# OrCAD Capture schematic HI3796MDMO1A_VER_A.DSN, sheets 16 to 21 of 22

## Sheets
16 SHEET_16: size Custom
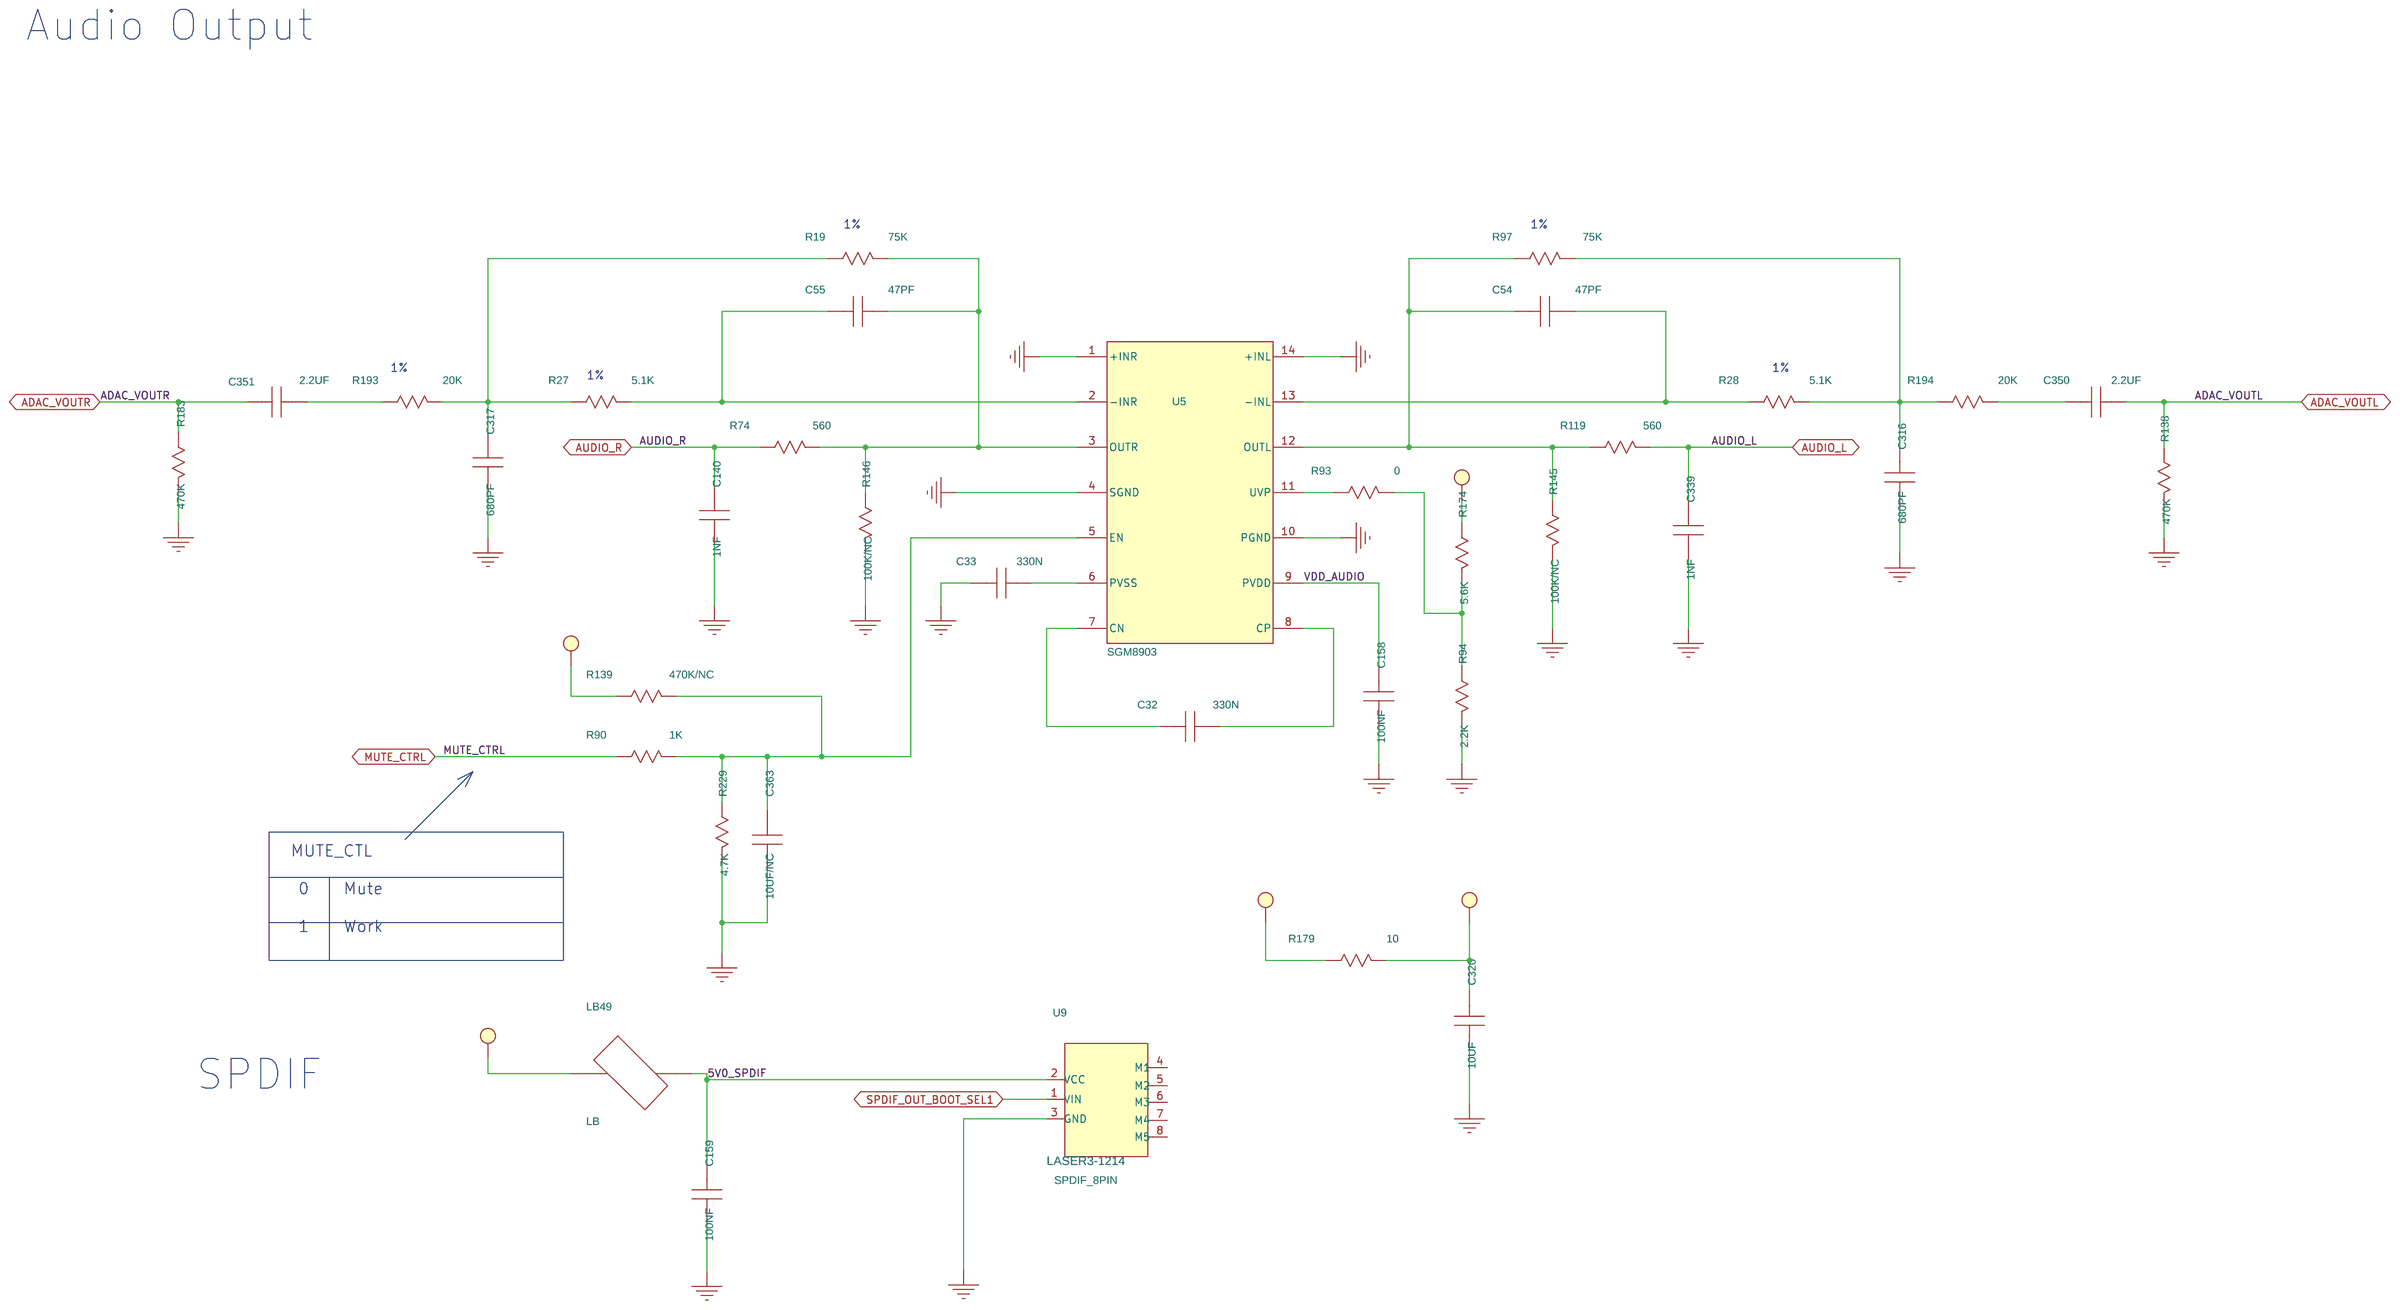
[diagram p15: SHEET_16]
17 SHEET_17: size B
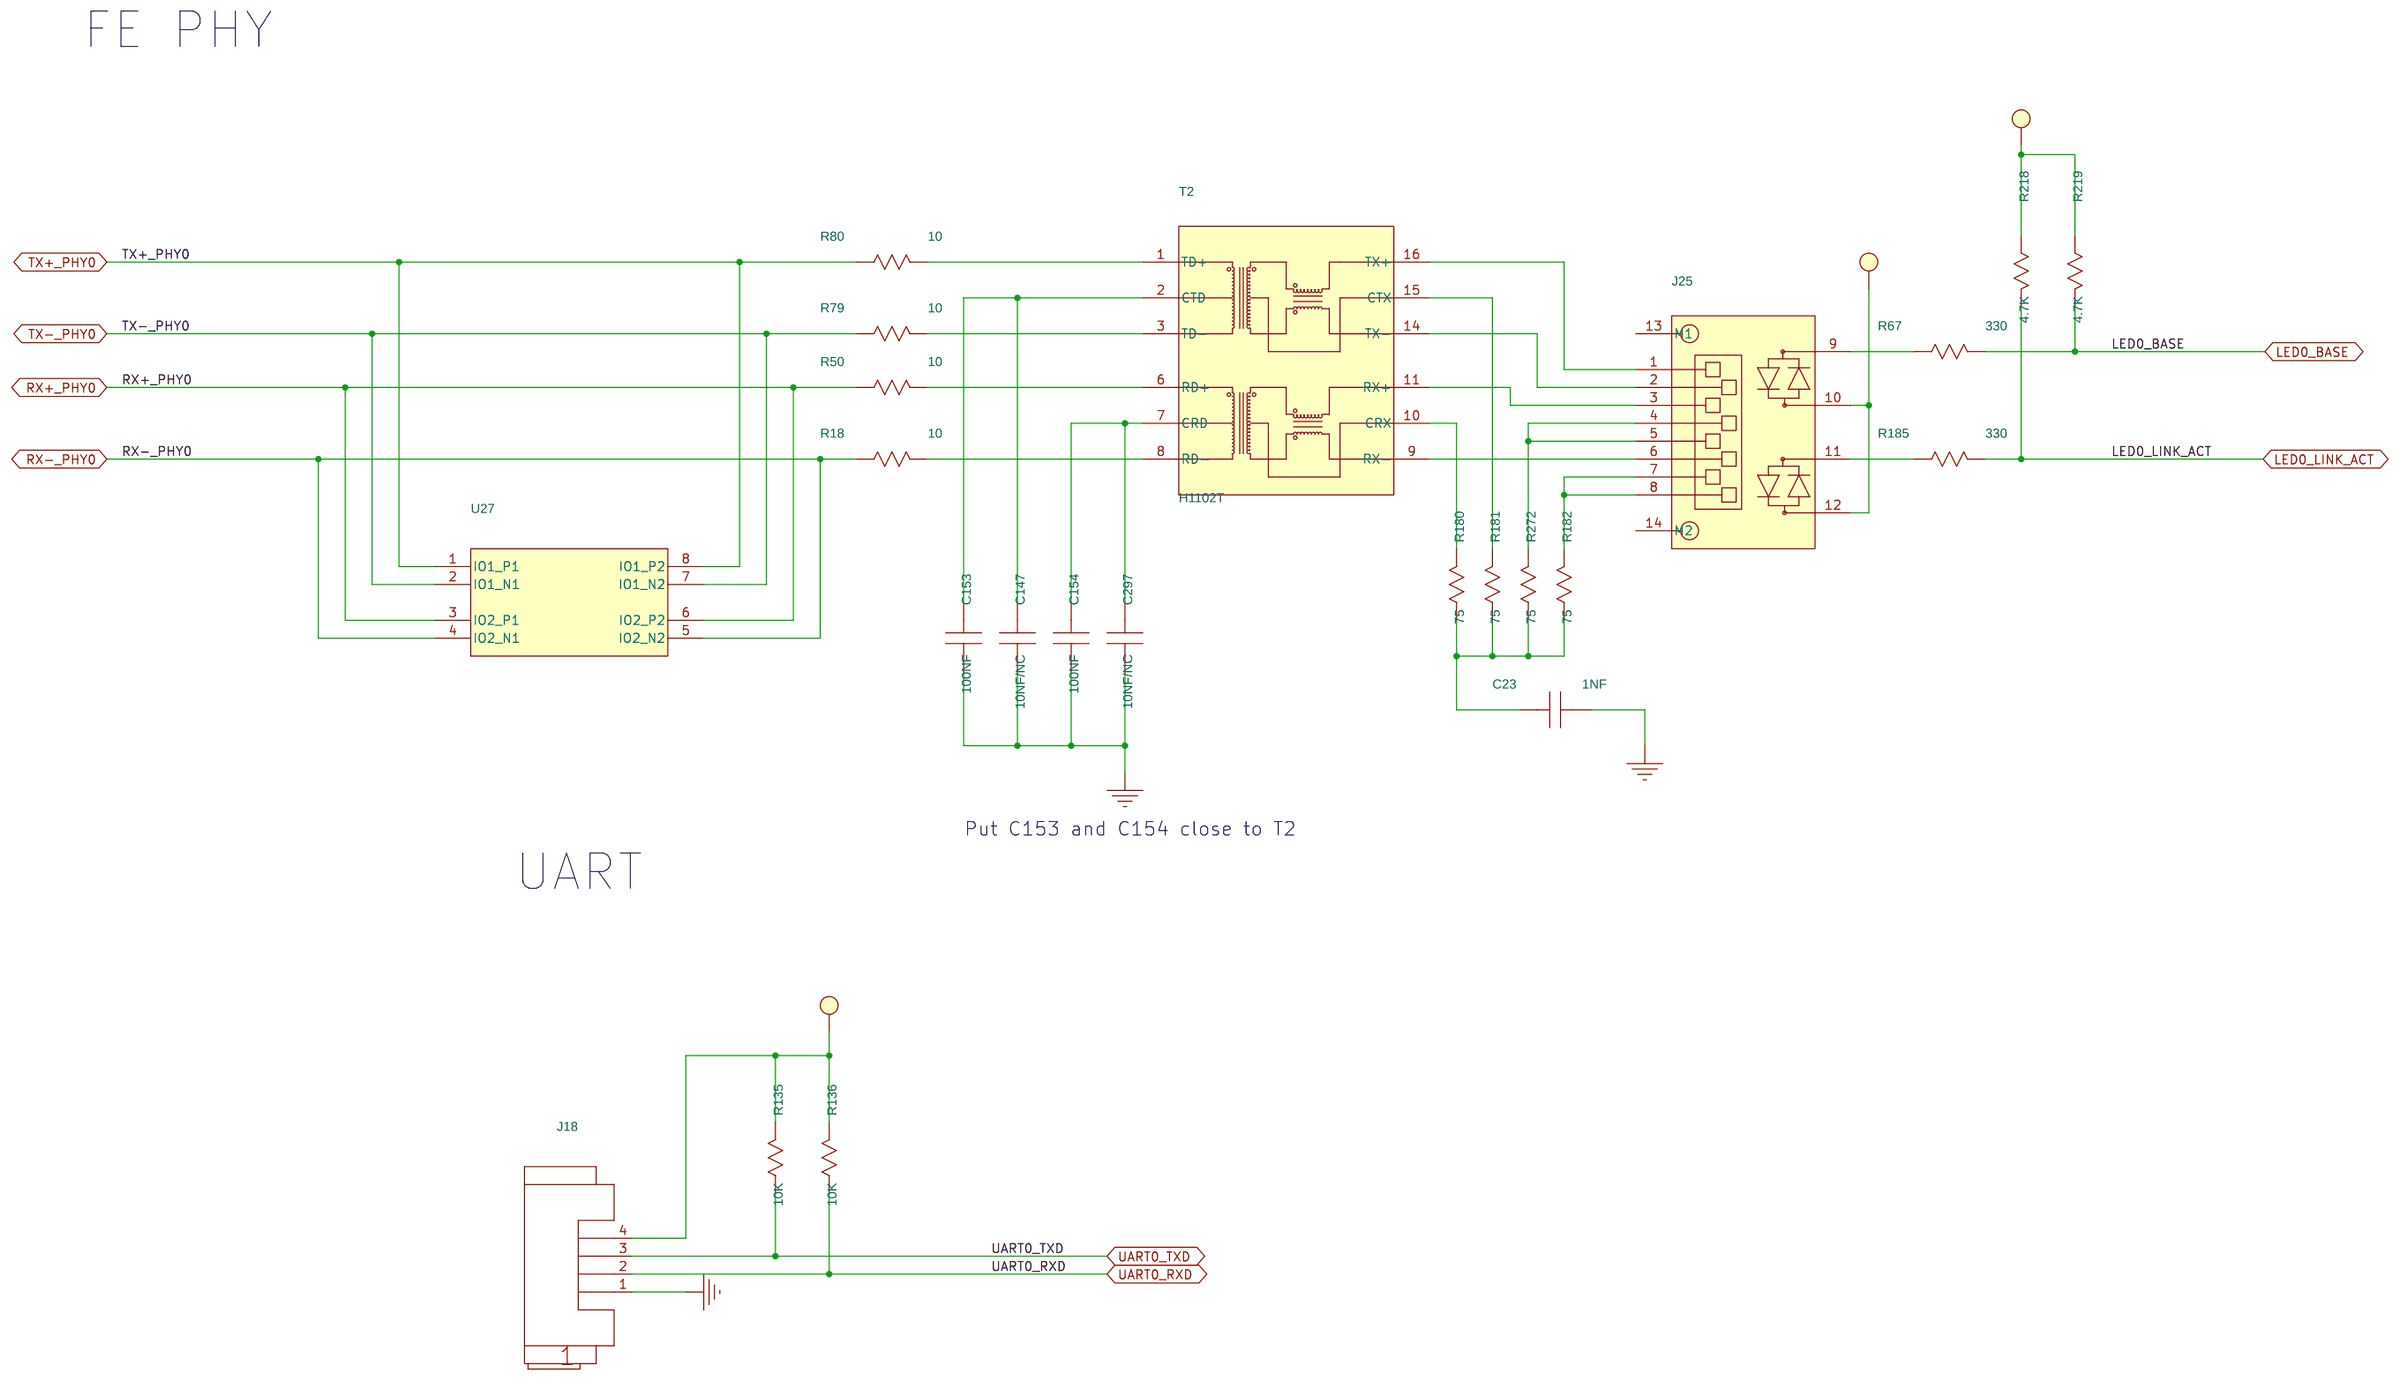
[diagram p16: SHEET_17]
18 SHEET_18: size B
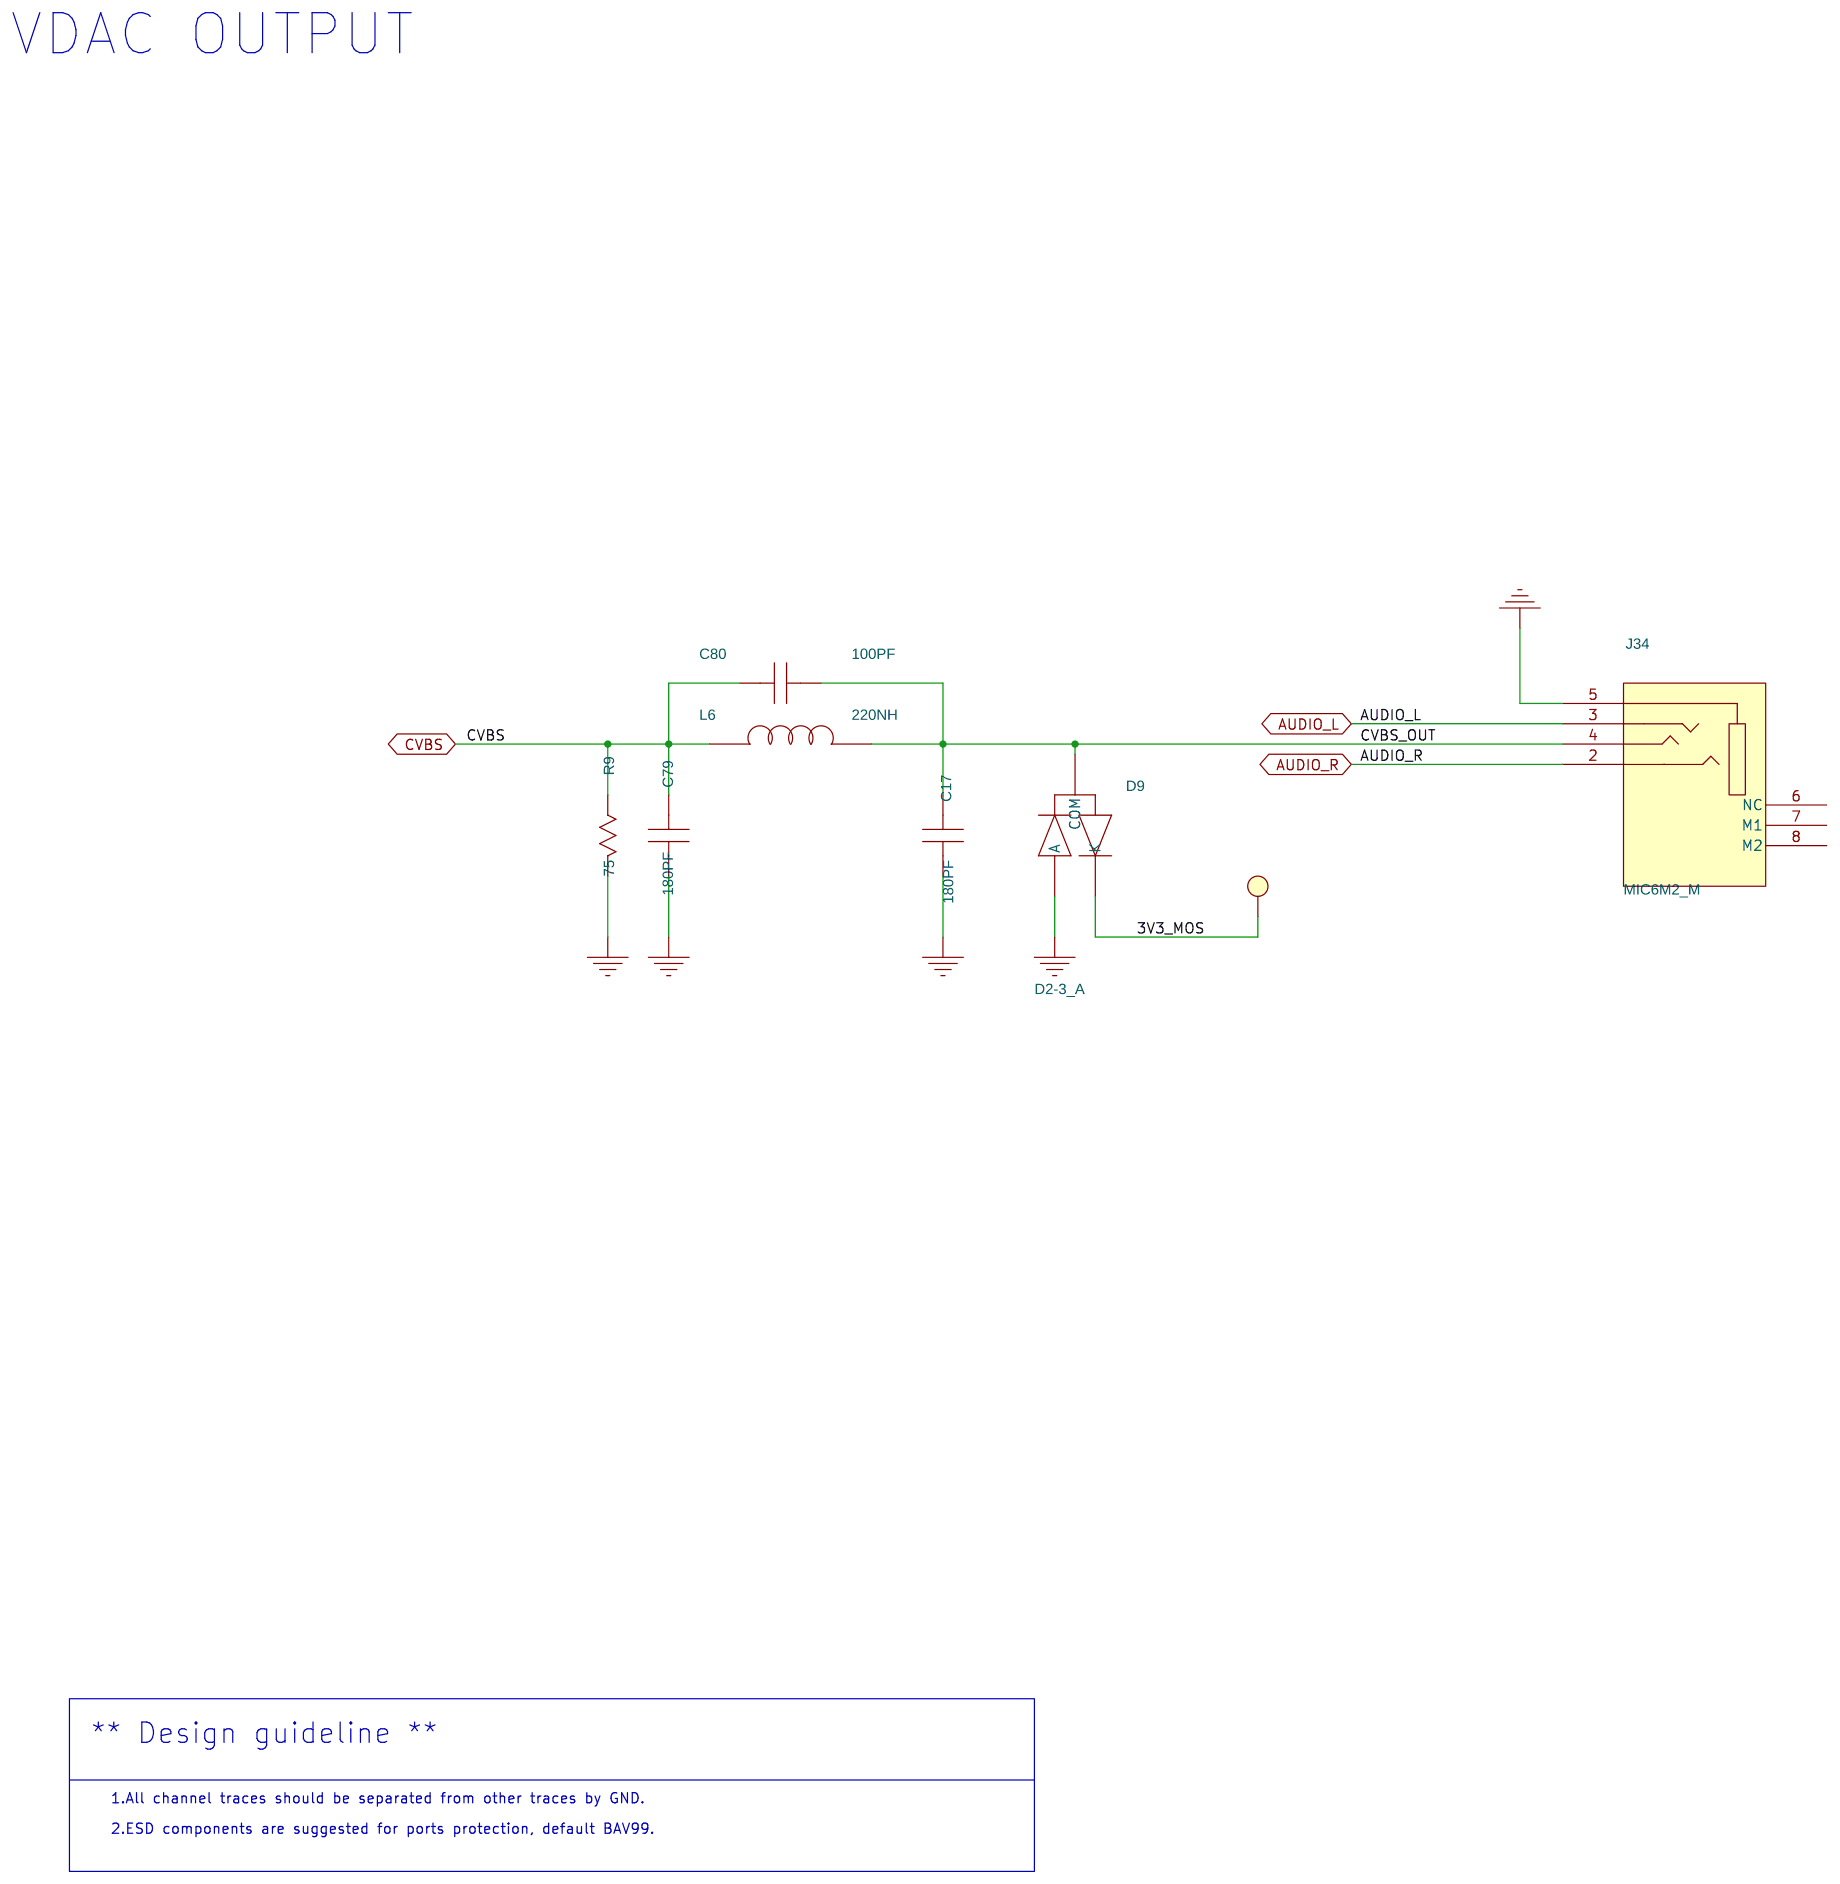
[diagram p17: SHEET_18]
19 SHEET_19: size B
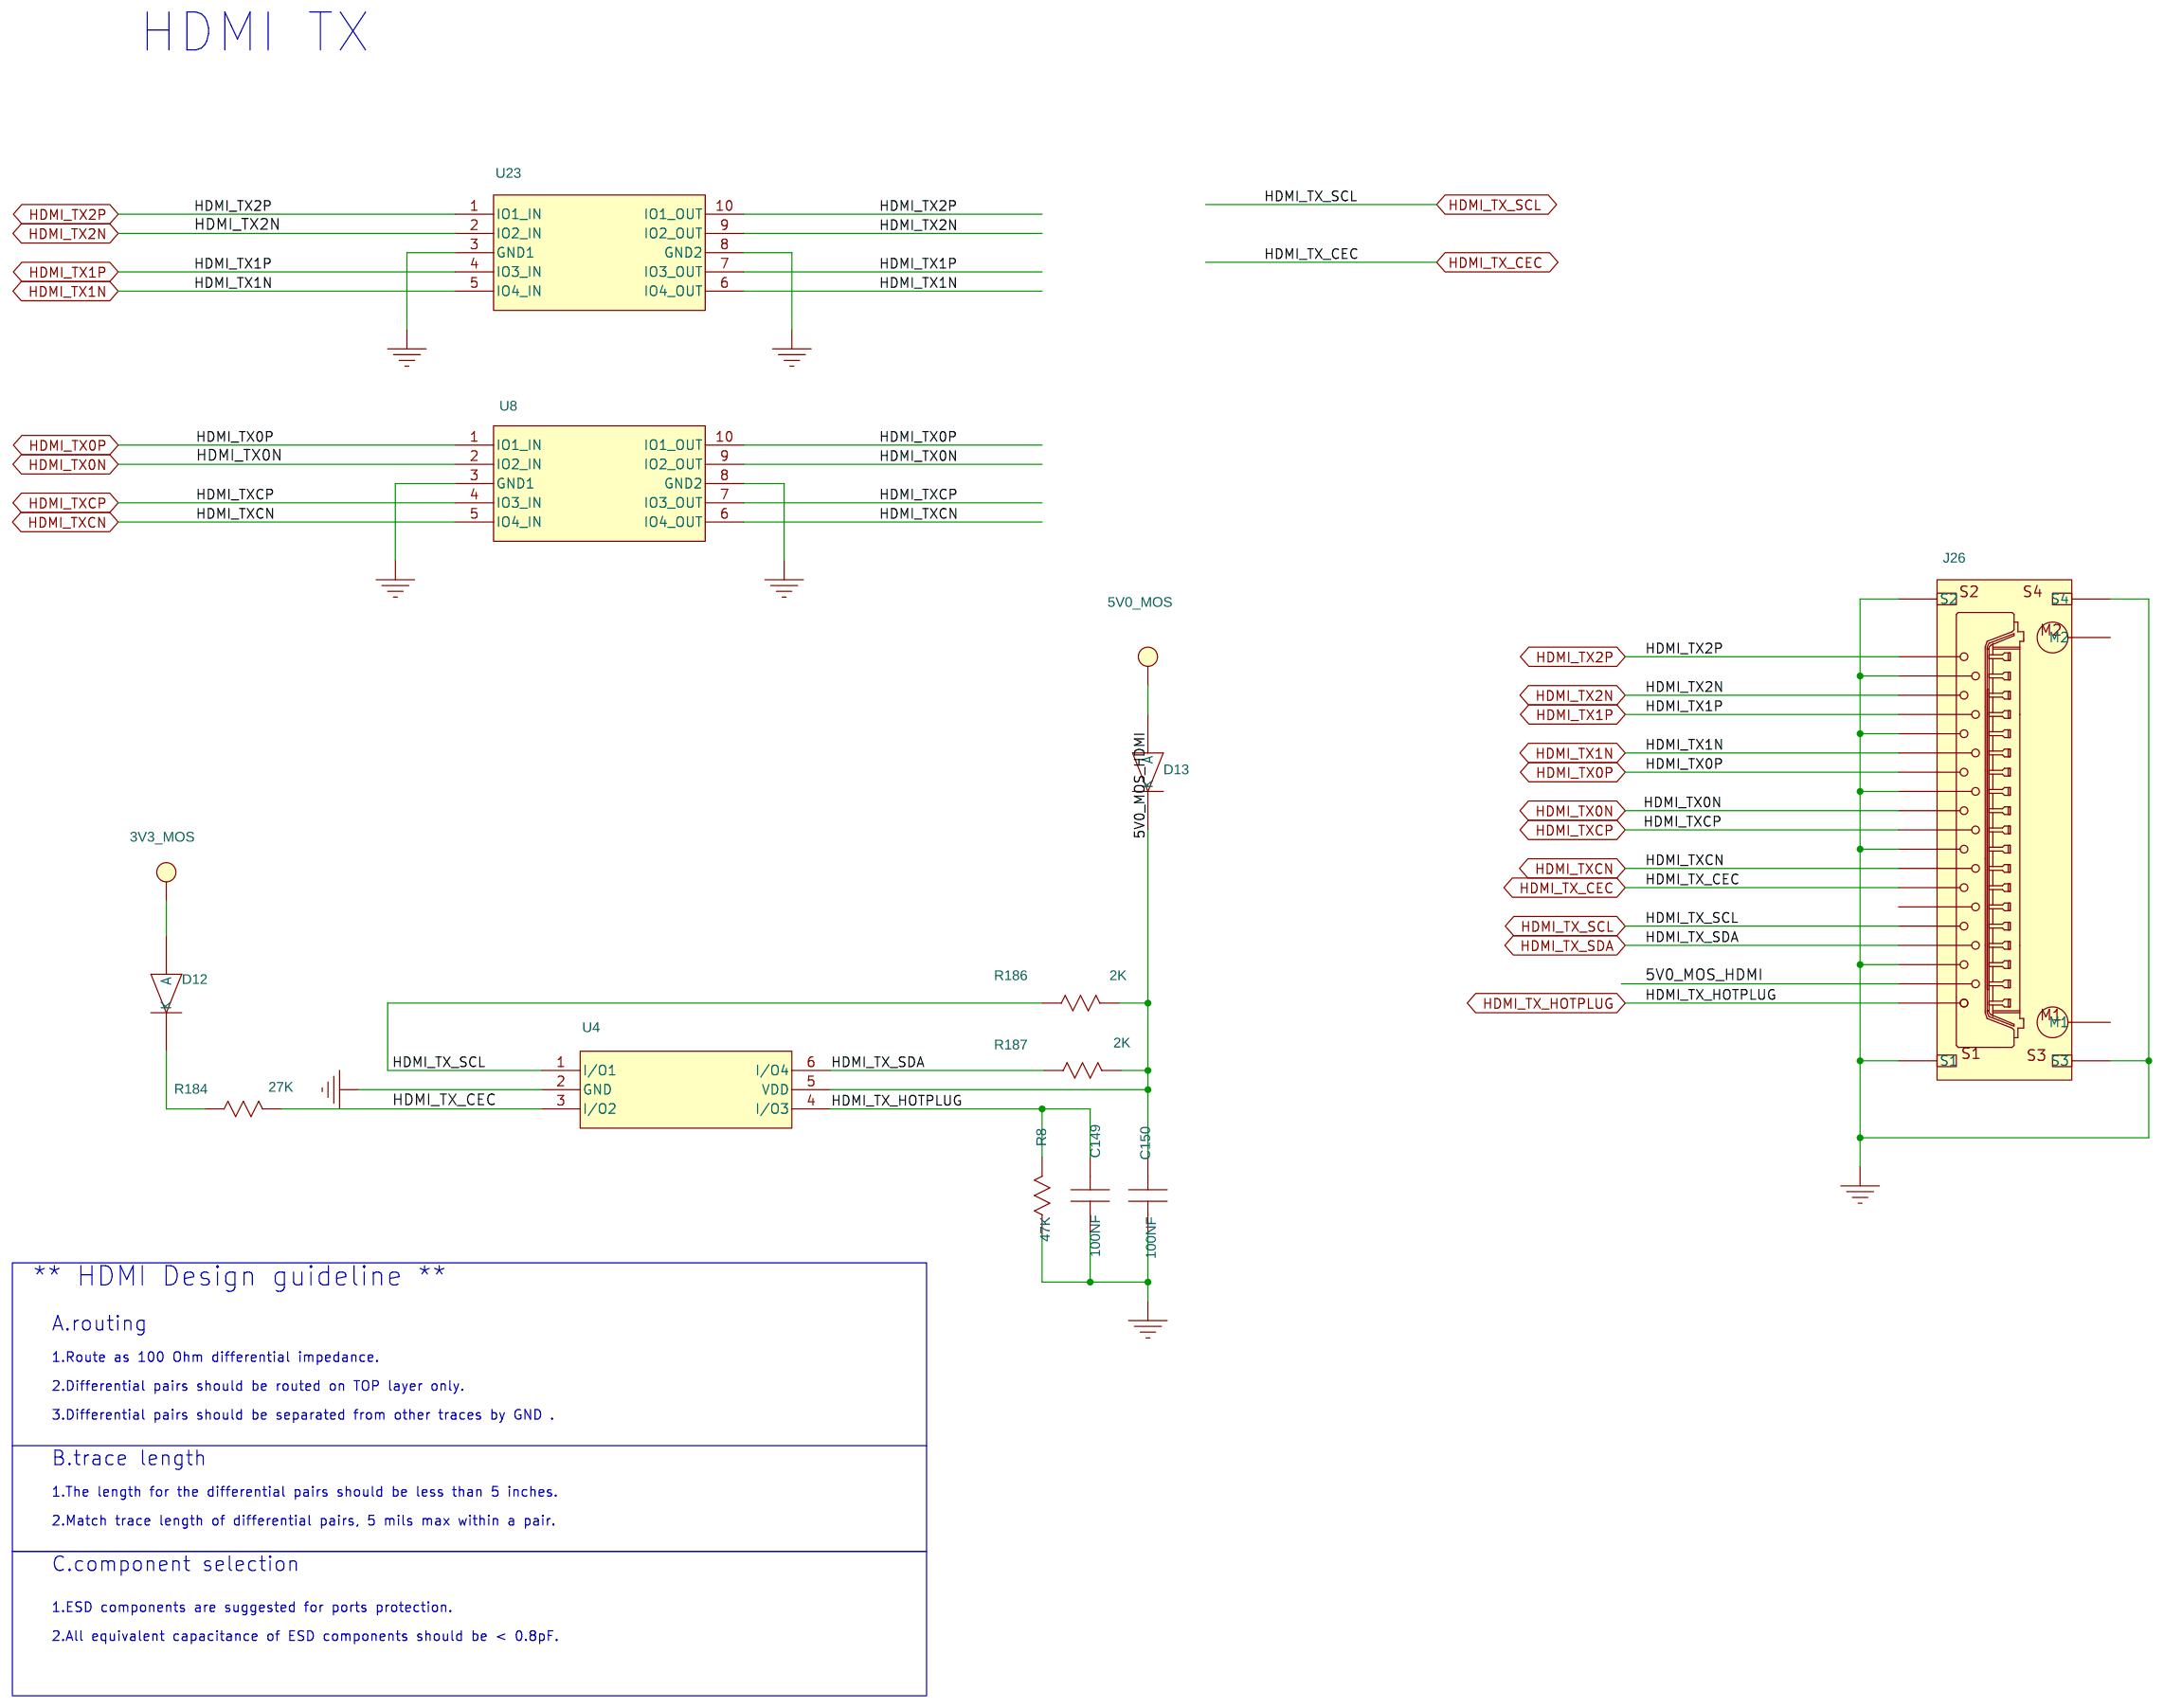
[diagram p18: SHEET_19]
20 SHEET_20: size B
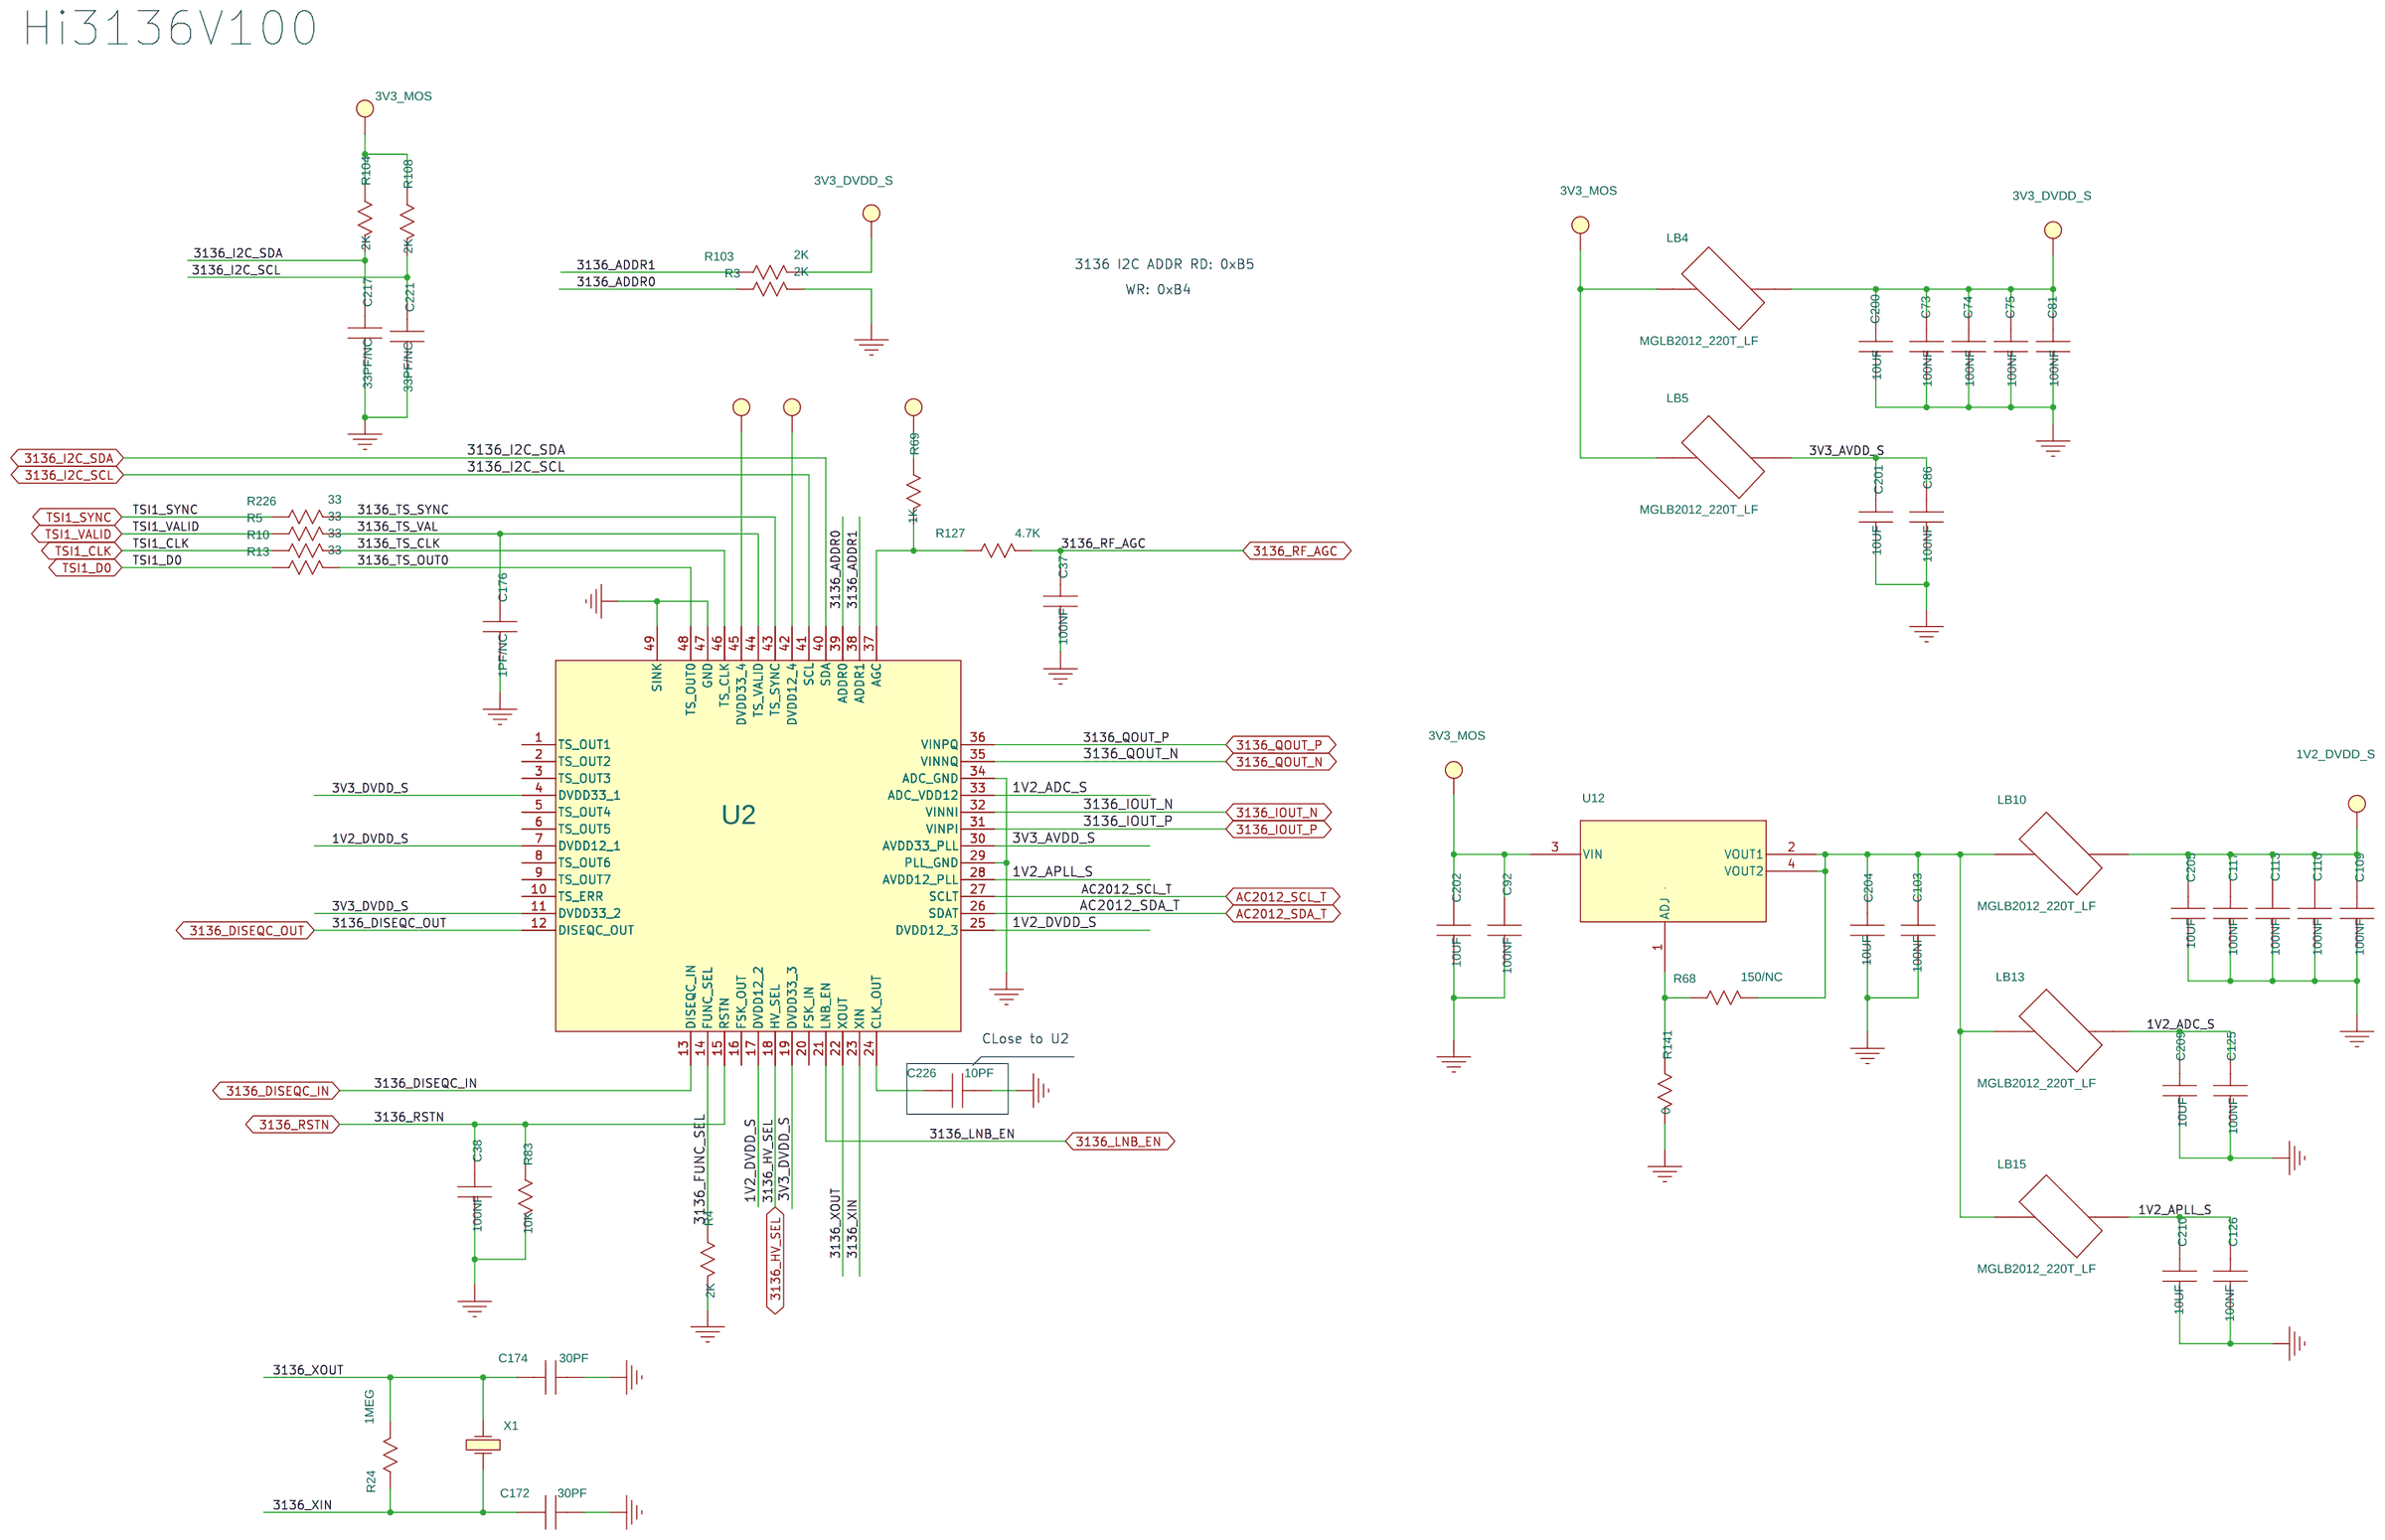
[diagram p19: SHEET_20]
21 SHEET_21: size Custom
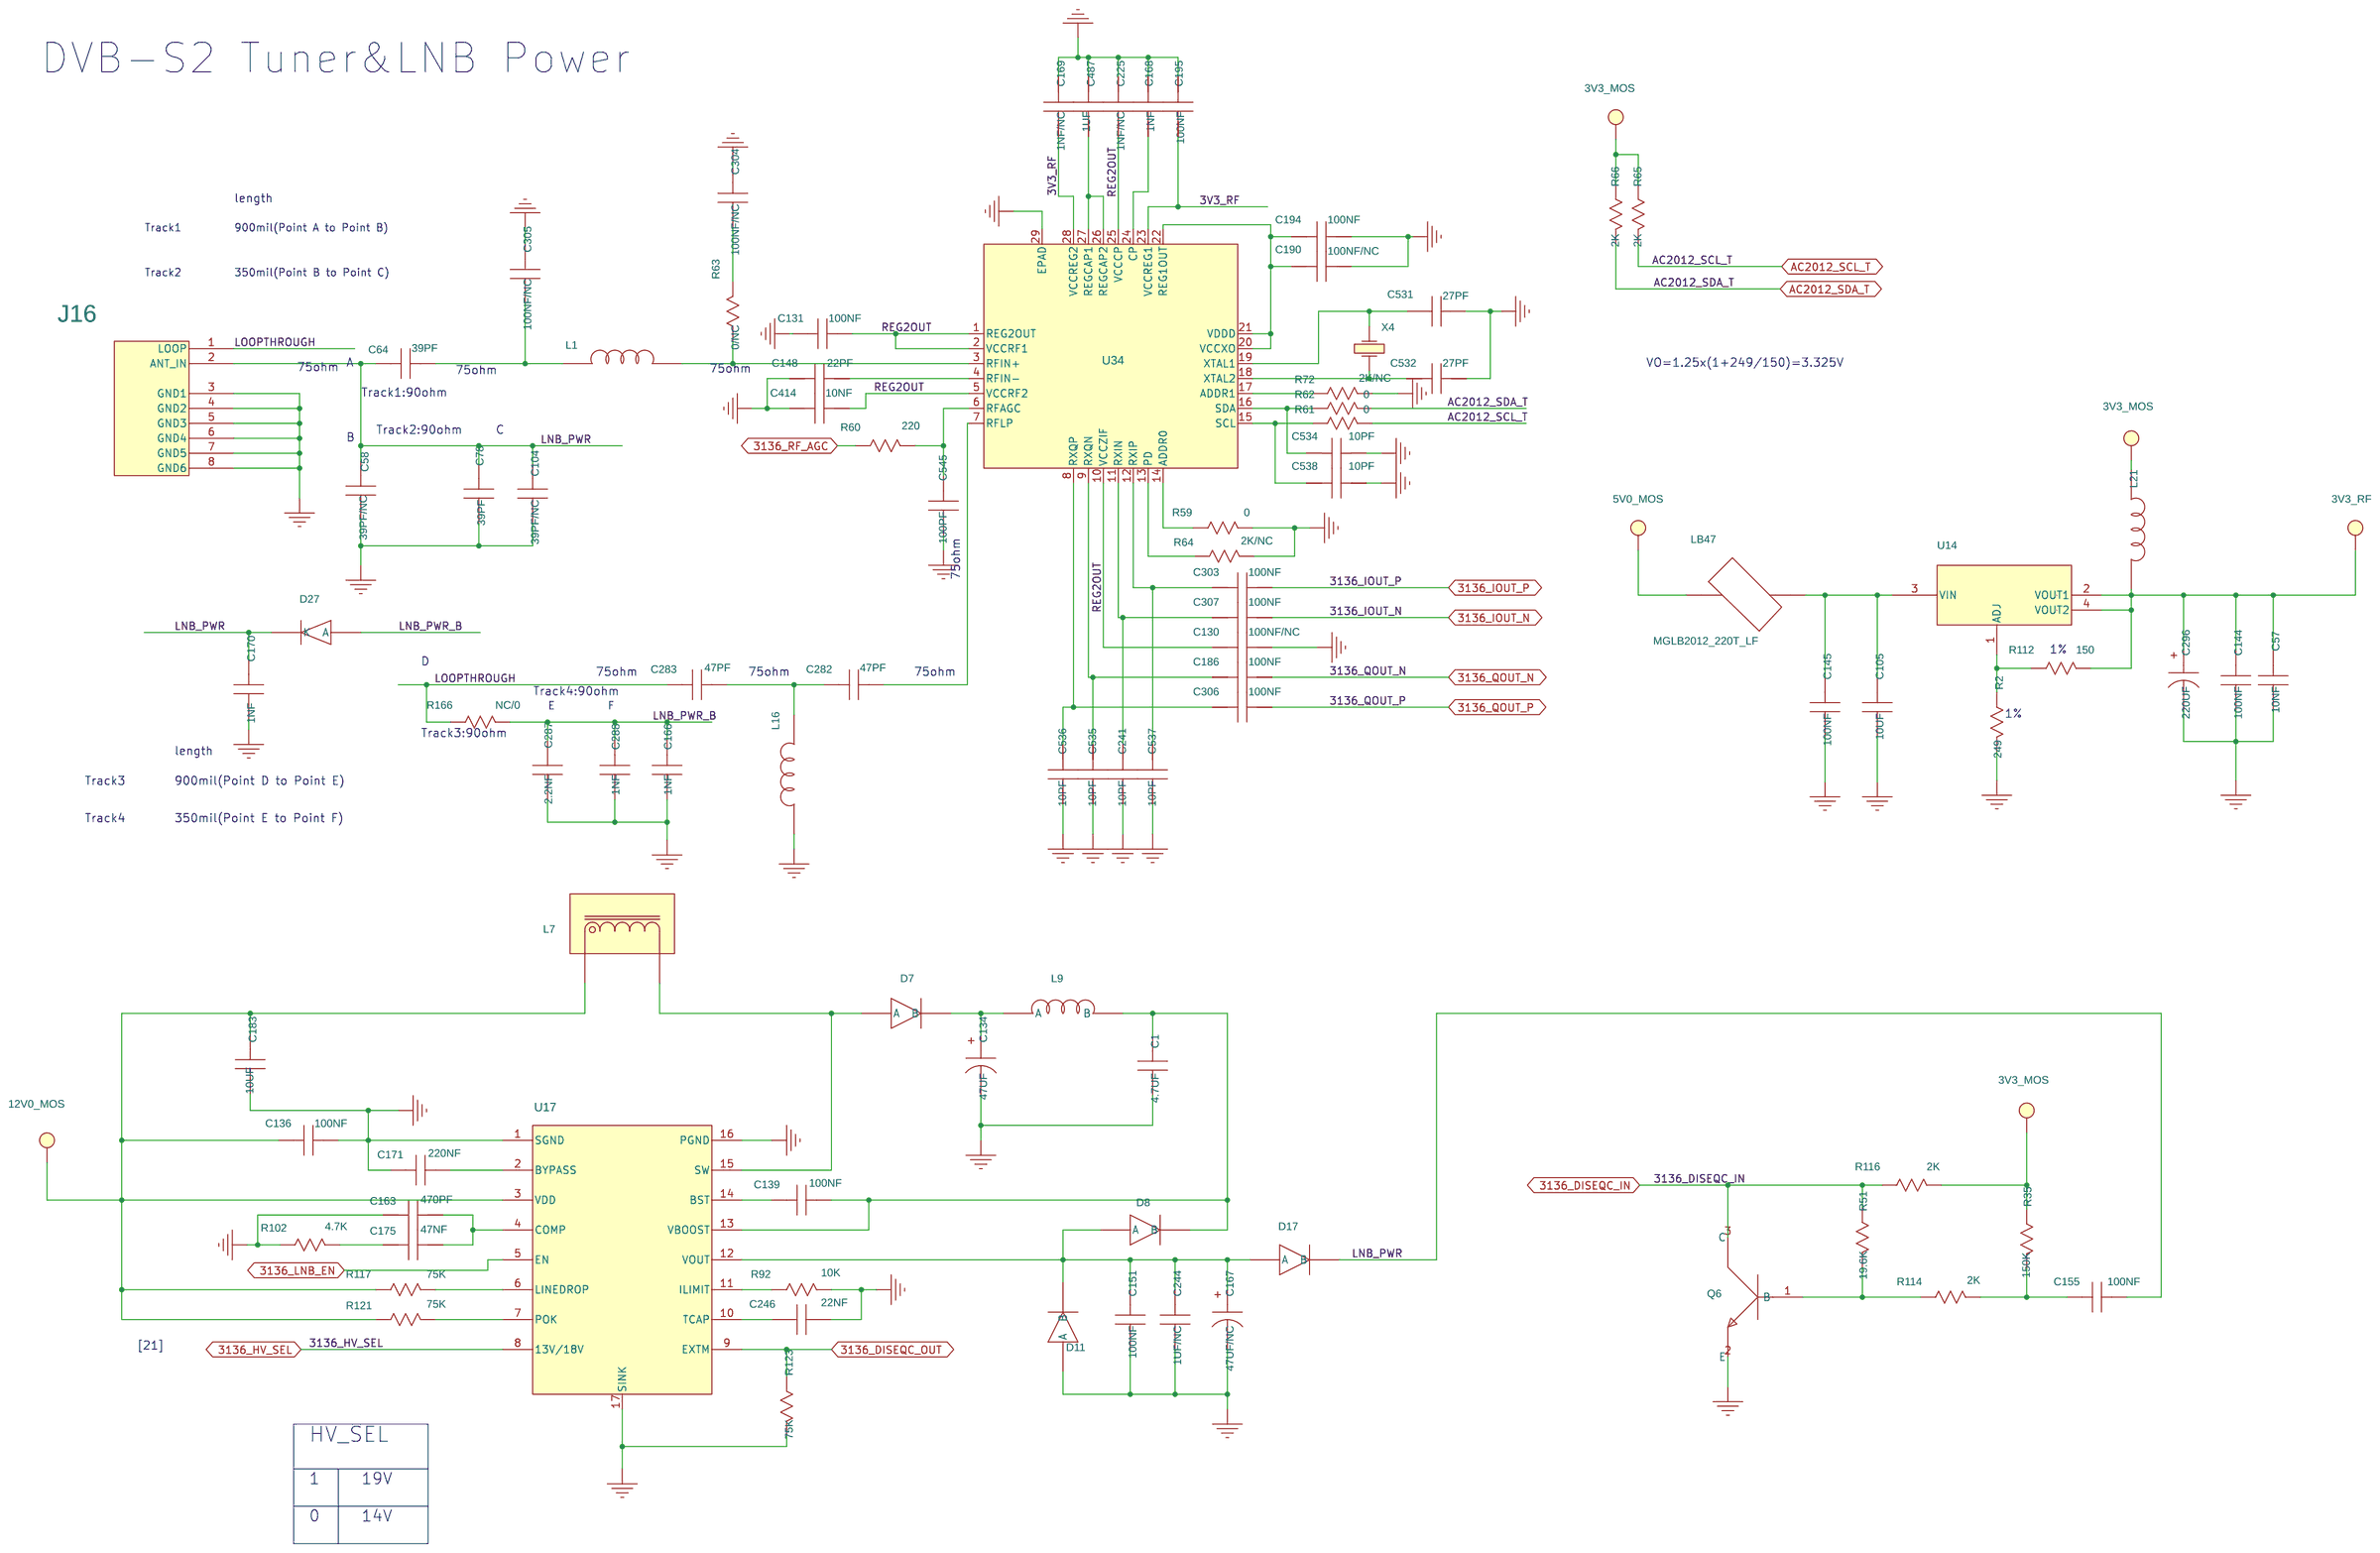
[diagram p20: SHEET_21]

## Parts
sheet SHEET_16
C32  330N  [HSC0402]
C33  330N  [HSC0402]
C54  47PF  [SC0402]
C55  47PF  [SC0402]
C140  1NF  [SC0402]
C158  100NF  [SC0402]
C159  100NF  [SC0402]
C316  680PF  [SC0402]
C317  680PF  [SC0402]
C320  10UF  [SC0603]
C339  1NF  [SC0402]
C350  2.2UF  [SC0603]
C351  2.2UF  [SC0603]
C363  10UF/NC  [SC0603]
LB49  LB  [SL0805]
R19  75K  [SR0603]
R27  5.1K  [SR0603]
R28  5.1K  [SR0603]
R74  560  [HSR0402]
R90  1K  [SR0402]
R93  0  [SR0402]
R94  2.2K  [SR0402]
R97  75K  [SR0603]
R119  560  [HSR0402]
R138  470K  [SR0402]
R139  470K/NC  [SR0402]
R145  100K/NC  [SR0402]
R146  100K/NC  [SR0402]
R174  5.6K  [SR0402]
R179  10  [SR0603]
R183  470K  [SR0402]
R193  20K  [SR0402]
R194  20K  [SR0402]
R229  4.7K  [SR0402]
U5  SGM8903  [SGM8903]
U9  SPDIF_8PIN  [LASER3-1214]
sheet SHEET_17
C23  1NF  [SC1206]
C147  10NF/NC  [SC0402]
C153  100NF  [SC0402]
C154  100NF  [SC0402]
C297  10NF/NC  [SC0402]
J18  WBC1X41  [WBC0104-49T]
J25  MJ8-L  [MJ8-RLY]
R18  10  [SR0402]
R50  10  [SR0402]
R67  330  [SR0402]
R79  10  [SR0402]
R80  10  [SR0402]
R135  10K  [SR0402]
R136  10K  [SR0402]
R180  75  [SR0805]
R181  75  [SR0805]
R182  75  [SR0805]
R185  330  [SR0402]
R218  4.7K  [SR0402]
R219  4.7K  [SR0402]
R272  75  [SR0805]
T2  000-7090-37R  [STFM16-50-285]
U27  /NC  [RN8-0402]
sheet SHEET_18
C17  180PF  [SC0402]
C79  180PF  [SC0402]
C80  100PF  [SC0402]
D9  D2-3_A  [SOT23]
J34  MIC6M2_M  [VAF6-1107]
L6  220NH  [SL0402]
R9  75  [SR0402]
sheet SHEET_19
C149  100NF  [SC0402]
C150  100NF  [SC0402]
D12  D_A  [HSOD323A]
D13  D_A  [HSOD323A]
J26  0  [WBC0119-20R-A]
R8  47K  [SR0402]
R184  27K  [SR0402]
R186  2K  [SR0402]
R187  2K  [SR0402]
U4  CS0806U  [SOT23A-6L]
U8  CS0806S  [DFN2510P10E]
U23  CS0806S  [DFN2510P10E]
sheet SHEET_20
C37  100NF  [SC0402]
C38  100NF  [SC0402]
C73  100NF  [SC0402]
C74  100NF  [SC0402]
C75  100NF  [SC0402]
C81  100NF  [SC0402]
C86  100NF  [SC0402]
C92  100NF  [SC0402]
C103  100NF  [SC0402]
C109  100NF  [SC0402]
C110  100NF  [SC0402]
C113  100NF  [SC0402]
C117  100NF  [SC0402]
C125  100NF  [SC0402]
C126  100NF  [SC0402]
C172  30PF  [SC0402]
C174  30PF  [SC0402]
C176  1PF/NC  [SC0402]
C200  10UF  [SC0603]
C201  10UF  [SC0603]
C202  10UF  [SC0603]
C204  10UF  [SC0603]
C205  10UF  [SC0603]
C209  10UF  [SC0603]
C210  10UF  [SC0603]
C217  33PF/NC  [SC0402]
C221  33PF/NC  [SC0402]
C226  10PF  [SC0402]
LB4  LB  [SL0805]
LB5  LB  [SL0805]
LB10  LB  [SL0805]
LB13  LB  [SL0805]
LB15  LB  [SL0805]
R3  2K  [SR0402]
R4  2K  [SR0402]
R5  33  [SR0402]
R10  33  [SR0402]
R13  33  [SR0402]
R24  1MEG  [SR0402]
R68  150/NC  [SR0402]
R69  1K  [SR0402]
R83  10K  [SR0402]
R103  2K  [SR0402]
R104  2K  [SR0402]
R108  2K  [SR0402]
R127  4.7K  [SR0402]
R141  0  [SR0603]
R226  33  [SR0402]
U2  HI3136V100  [MLF48B-040-0606L]
U12  AZ1117-ADJ  [TO-252]
X1  24MHZ  [SX2-1205]
sheet SHEET_21
C1  4.7UF  [SC1210]
C57  10NF  [HSC0402]
C58  39PF/NC  [SC0402]
C64  39PF  [SC0402]
C78  39PF  [SC0402]
C104  39PF/NC  [SC0402]
C105  10UF  [SC1206]
C130  100NF/NC  [SC0402]
C131  100NF  [SC0402]
C134  47UF  [SCAPC2-0606]
C136  100NF  [SC0402]
C139  100NF  [SC0402]
C144  100NF  [SC0402]
C145  100NF  [SC0402]
C148  22PF  [SC0402]
C151  100NF  [SC0402]
C155  100NF  [SC0402]
C163  470PF  [SC0402]
C166  1NF  [SC0402]
C167  47UF/NC  [SCAPC2-0606]
C168  1NF  [SC0603]
C169  1NF/NC  [SC0603]
C170  1NF  [SC0402]
C171  220NF  [SC0805]
C175  47NF  [SC0402]
C183  10UF  [SC1206]
C186  100NF  [SC0402]
C190  100NF/NC  [SC0402]
C194  100NF  [SC0402]
C195  100NF  [SC0402]
C225  1NF/NC  [SC0603]
C241  10PF  [SC0402]
C244  1UF/NC  [SC1206]
C246  22NF  [SC0603]
C282  47PF  [SC0402]
C283  47PF  [SC0402]
C287  2.2NF  [SC0402]
C288  1NF  [SC0402]
C296  220UF  [SAC6666]
C303  100NF  [SC0402]
C304  100NF/NC  [SC0402]
C305  100NF/NC  [SC0402]
C306  100NF  [SC0402]
C307  100NF  [SC0402]
C414  10NF  [SC0402]
C487  1UF  [SC0603]
C531  27PF  [SC0402]
C532  27PF  [SC0402]
C534  10PF  [SC0402]
C535  10PF  [SC0402]
C536  10PF  [SC0402]
C537  10PF  [SC0402]
C538  10PF  [SC0402]
C545  100PF  [SC0402]
D7  DIODE  [SD1714A]
D8  DIODE  [SD1714A]
D11  DIODE  [SD1714A]
D17  DIODE  [SD1714A]
D27  D_A  [HSOD323A]
J16  JTDA18250  [JTDA18250]
L1  3.3NH  [SL0402]
L7  22UH/2A  [L6X6X4_5]
L9  1UH  [SWPA4020S]
L16  NC/3.3NH  [SL0402]
L21  4.7UH/NC  [HSL1007]
LB47  LB  [SL0805]
Q6  NPN-BEC  [SOT23]
R2  249  [SR0603]
R35  150K  [SR0603]
R51  19.6K  [SR0603]
R59  2K/NC  [SR0402]
R60  220  [SR0402]
R61  0  [SR0402]
R62  0  [SR0402]
R63  0/NC  [SR0402]
R64  0  [SR0402]
R65  2K  [SR0402]
R66  2K  [SR0402]
R72  2K/NC  [SR0402]
R92  10K  [SR0402]
R102  4.7K  [SR0402]
R112  150  [SR0402]
R114  2K  [SR0603]
R116  2K  [SR0603]
R117  75K  [SR0402]
R121  75K  [SR0402]
R123  75K  [SR0402]
R166  NC/0  [SR0402]
U14  LM1117-ADJ  [SOT223A]
U17  MP8126  [TSSOP16EP]
U34  AV2012  [QFN28B-040-0404LH]
X4  27MHZ  [SX2-1205]

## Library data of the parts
C32 C33 = C_0: %195%%232%%202%%246%: SMD陶瓷电容-6.3V-330NF-+/-10%-X5R-0402-终端专用; %208%%161%%192%%224%%195%%251%%179%%198%: SMD陶瓷电容; CODE: 8070953; COMPONENT_HIGH_MAX: 0.55MM; DEVICE: C1005X5R0J334K
C54 C55 C282 C283 = C_0: %182%%238%%182%%168%%185%%164%%215%%247%%181%%231%%209%%185%(V): 50; %195%%232%%202%%246%: SMD陶瓷电容-50V-0.047NF-+/-5%-NP0-0402; %208%%161%%192%%224%%195%%251%%179%%198%: SMD陶瓷电容; CODE: 8070549; COMPONENT_HIGH_MAX: 0.55MM; DEVICE: C0402C470J5GAC_7867
C140 C166 C170 C288 C339 = C_0: %182%%238%%182%%168%%185%%164%%215%%247%%181%%231%%209%%185%(V): 50; %195%%232%%202%%246%: SMD陶瓷电容-50V-1NF-+/-10%-X7R-0402-BT; %208%%161%%192%%224%%195%%251%%179%%198%: SMD陶瓷电容; CODE: 8070531; COMPONENT_HIGH_MAX: 0.55MM; DEVICE: 04025C102KAT2A
C153 C154 C158 C159 = C_0: %182%%238%%182%%168%%185%%164%%215%%247%%181%%231%%209%%185%(V): 16; %195%%232%%202%%246%: SMD陶瓷电容-16V-100NF-±10%-X7R-0402; %208%%161%%192%%224%%195%%251%%179%%198%: SMD陶瓷电容; CODE: 8070614; COMPONENT_HIGH_MAX: 0.6MM; DEVICE: RMEMK105BJ104KV_FR
C316 C317 = C_0: %182%%238%%182%%168%%185%%164%%215%%247%%181%%231%%209%%185%(V): 50; %195%%232%%202%%246%: SMD陶瓷电容-50V-0.68NF-+/-5%-NP0-0402-供电专用-供电专用; %208%%161%%192%%224%%195%%251%%179%%198%: SMD陶瓷电容; CODE: 8070853; COMPONENT_HIGH_MAX: 0.55MM; DEVICE: C0402C681J5GAC7867
C200-C202 C204 C205 C209 C210 C320 C363 = C_0: %182%%238%%182%%168%%185%%164%%215%%247%%181%%231%%209%%185%(V): 6.3; %195%%232%%202%%246%: SMD陶瓷电容-6.3V-10000NF-+/-20%-X5R-0603-BT,TS16949; %208%%161%%192%%224%%195%%251%%179%%198%: SMD陶瓷电容; CODE: 8070649; COMPONENT_HIGH_MAX: 0.9MM; DEVICE: C1608X5R0J106MT0A0E
C350 C351 = C_0: %182%%238%%182%%168%%185%%164%%215%%247%%181%%231%%209%%185%(V): 10; %195%%232%%202%%246%: SMD陶瓷电容-10V-2200NF-+/-10%-X5R-0603; %208%%161%%192%%224%%195%%251%%179%%198%: SMD陶瓷电容; CODE: 8070573; COMPONENT_HIGH_MAX: 0.9MM; DEVICE: GRM188R61A225KE34D
LB47 LB49 = LB_v2: %195%%232%%202%%246%: EMI磁珠-220OHM-0.05OHM-2A-0805; %208%%161%%192%%224%%195%%251%%179%%198%: EMI磁珠; CODE: 10070012; COMPONENT_HIGH_MAX: 1.05MM; DEVICE: MGLB2012_220T_LF
R19 R97 = R_0: %182%%238%%182%%168%%185%%166%%194%%202%(W): 0.1; %195%%232%%202%%246%: 片式厚膜电阻器-0.1W-75000OHM-+/-1% -0603; %208%%161%%192%%224%%195%%251%%179%%198%: 片式厚膜电阻器; %215%%232%%214%%181%%212%%202%%208%%237%%198%%171%%178%%238%: +/-1%; CODE: 7091238; COMPONENT_HIGH_MAX: 0.55MM; DEVICE: RK73H1JTTD7502F
R27 R28 = R_0: %182%%238%%182%%168%%185%%166%%194%%202%(W): 0.1; %195%%232%%202%%246%: 片式厚膜电阻器-0.1W-5100OHM-+/-1%-0603; %208%%161%%192%%224%%195%%251%%179%%198%: 片式厚膜电阻器; %215%%232%%214%%181%%212%%202%%208%%237%%198%%171%%178%%238%: +/-1%; CODE: 7091295; COMPONENT_HIGH_MAX: 0.55MM; DEVICE: RC0603FR_075K1L
R74 R119 = R_0: %195%%232%%202%%246%: 片式厚膜电阻器-0.0625W-560OHM-+/-5%-0402-终端专用-终端专用; %208%%161%%192%%224%%195%%251%%179%%198%: 片式厚膜电阻器; CODE: 7091285; COMPONENT_HIGH_MAX: 0.4MM; DEVICE: RC0402JR_07560RL
R90 = R_0: %182%%238%%182%%168%%185%%166%%194%%202%(W): 0.06; %195%%232%%202%%246%: 片式厚膜电阻器-0.0625W-1000OHM-±5%-0402; %208%%161%%192%%224%%195%%251%%179%%198%: 片式厚膜电阻器; %215%%232%%214%%181%%212%%202%%208%%237%%198%%171%%178%%238%: ±5%; CODE: 7090809; COMPONENT_HIGH_MAX: 0.4MM; DEVICE: RC0402JR_071KL
R61-R64 R93 R166 = R_0: %182%%238%%182%%168%%185%%166%%194%%202%(W): 0.06; %195%%232%%202%%246%: 片式厚膜电阻器-0.0625W-0OHM-< 50MOHM-0402-1A-BT; %208%%161%%192%%224%%195%%251%%179%%198%: 片式厚膜电阻器; %215%%232%%214%%181%%212%%202%%208%%237%%198%%171%%178%%238%: < 50MOHM; CODE: 7090800; DEVICE: RC0402JR_070R
R94 = R_0: %182%%238%%182%%168%%185%%166%%194%%202%(W): 0.06; %195%%232%%202%%246%: 片式厚膜电阻器-0.0625W-2200OHM-+/-1%-0402--供电专用-07090810-供电专用; %208%%161%%192%%224%%195%%251%%179%%198%: 片式厚膜电阻器; %215%%232%%214%%181%%212%%202%%208%%237%%198%%171%%178%%238%: +/-1%; CODE: 7091537; COMPONENT_HIGH_MAX: 0.4MM; DEVICE: RC0402FR_072K2L2
R138 R183 = R_0: %182%%238%%182%%168%%185%%166%%194%%202%(W): 0.06; %195%%232%%202%%246%: 片式厚膜电阻器-0.0625W-470000OHM-±1%-0402; %208%%161%%192%%224%%195%%251%%179%%198%: 片式厚膜电阻器; %215%%232%%214%%181%%212%%202%%208%%237%%198%%171%%178%%238%: ±1%; CODE: 7090855; COMPONENT_HIGH_MAX: 0.4MM; DEVICE: RK73H1ETTP4703F
R139 = R_0: %182%%238%%182%%168%%185%%166%%194%%202%(W): 0.06; %195%%232%%202%%246%: 片式厚膜电阻器-0.0625W-470000OHM-+/-1%-0402; %208%%161%%192%%224%%195%%251%%179%%198%: 片式厚膜电阻器; %215%%232%%214%%181%%212%%202%%208%%237%%198%%171%%178%%238%: +/-1%; CODE: 7090855; COMPONENT_HIGH_MAX: 0.4MM; DEVICE: RK73H1ETTP4703F
R145 R146 = R_0: %182%%238%%182%%168%%185%%166%%194%%202%(W): 0.06; %195%%232%%202%%246%: 片式厚膜电阻器-0.0625W-100000OHM-+/-5%-0402-BT; %208%%161%%192%%224%%195%%251%%179%%198%: 片式厚膜电阻器; %215%%232%%214%%181%%212%%202%%208%%237%%198%%171%%178%%238%: +/-5%; CODE: 7090831; COMPONENT_HIGH_MAX: 0.4MM; DEVICE: RK73B1ELTP104J
R174 = R_0: %182%%238%%182%%168%%185%%166%%194%%202%(W): 0.06; %195%%232%%202%%246%: 片式厚膜电阻器-0.0625W-5600OHM-+/-1%-0402-BT; %208%%161%%192%%224%%195%%251%%179%%198%: 片式厚膜电阻器; %215%%232%%214%%181%%212%%202%%208%%237%%198%%171%%178%%238%: +/-1%; CODE: 7091275; COMPONENT_HIGH_MAX: 0.4MM; DEVICE: RK73H1ETTP5601F
R179 = R_0: %182%%238%%182%%168%%185%%166%%194%%202%(W): 0.1; %195%%232%%202%%246%: 片式厚膜电阻器-0.1W-10OHM-+/-5%-0603-TS16949; %208%%161%%192%%224%%195%%251%%179%%198%: 片式厚膜电阻器; %215%%232%%214%%181%%212%%202%%208%%237%%198%%171%%178%%238%: +/-5%; CODE: 7090264; COMPONENT_HIGH_MAX: 0.55MM; DEVICE: RC0603JR_0710R
R193 R194 = R_0: %182%%238%%182%%168%%185%%166%%194%%202%(W): 0.06; %195%%232%%202%%246%: 片式厚膜电阻器-0.0625W-20000OHM-+/-1%-0402-TS16949; %208%%161%%192%%224%%195%%251%%179%%198%: 片式厚膜电阻器; %215%%232%%214%%181%%212%%202%%208%%237%%198%%171%%178%%238%: +/-1%; CODE: 7091374; COMPONENT_HIGH_MAX: 0.4MM; DEVICE: RC_02W2002FT
R102 R127 R218 R219 R229 = R_0: %182%%238%%182%%168%%185%%166%%194%%202%(W): 0.06; %195%%232%%202%%246%: 片式厚膜电阻器-0.0625W-4700OHM-+/-5%-0402-BT; %208%%161%%192%%224%%195%%251%%179%%198%: 片式厚膜电阻器; %215%%232%%214%%181%%212%%202%%208%%237%%198%%171%%178%%238%: +/-5%; CODE: 7090793; COMPONENT_HIGH_MAX: 0.4MM; DEVICE: RK73B1ELTP472J
U5 = SGM8903: DEVICE: DIO2103_SGM8903
U9 = SPDIF_2: DEVICE: GP1FAV50TK0F
C23 = C_0: %182%%238%%182%%168%%185%%164%%215%%247%%181%%231%%209%%185%(V): 2000; %195%%232%%202%%246%: SMD陶瓷电容-2000V-1NF-+/-20%-X7R-1206; %208%%161%%192%%224%%195%%251%%179%%198%: SMD陶瓷电容; CODE: 8070439; COMPONENT_HIGH_MAX: 1.52MM; DEVICE: 1206GC102MAT1A
C147 C297 = C_0: %182%%238%%182%%168%%185%%164%%215%%247%%181%%231%%209%%185%(V): 16; %195%%232%%202%%246%: SMD陶瓷电容-16V-10NF-+/-10%-X7R-0402-BT,TS16949; %208%%161%%192%%224%%195%%251%%179%%198%: SMD陶瓷电容; CODE: 8070449; COMPONENT_HIGH_MAX: 0.55MM; DEVICE: GRM155R71C103KA01D
J18 = WBC1X41_0: %195%%232%%202%%246%: 普通插座-4PIN-单排-直式-1.25MM-2MM-THT-1A; %208%%161%%192%%224%%195%%251%%179%%198%: 普通插座; CODE: 14100167; COMPONENT_HIGH_MAX: 4.2MM; DEVICE: SDW12501_4A_HW
J25 = MJ8-L_0: %195%%232%%202%%246%: 网口连接器-单排-单端口-8PIN-8BIT-非屏蔽-模型插座/侧面插入型-引脚长2.54MM-带固定脚/带灯; %208%%161%%192%%224%%195%%251%%179%%198%: 网口连接器; COMPONENT_HIGH_MAX: 13.2MM; DEVICE: 406533_1
R18 R50 R79 R80 = R_0: %182%%238%%182%%168%%185%%166%%194%%202%(W): 0.06; %195%%232%%202%%246%: 片式厚膜电阻器-0.0625W-10OHM-+/-5%-0402; %208%%161%%192%%224%%195%%251%%179%%198%: 片式厚膜电阻器; %215%%232%%214%%181%%212%%202%%208%%237%%198%%171%%178%%238%: +/-5%; CODE: 7090730; COMPONENT_HIGH_MAX: 0.4MM; DEVICE: RC0402JR_0710R
R67 R185 = R_0: %182%%238%%182%%168%%185%%166%%194%%202%(W): 0.06; %195%%232%%202%%246%: 片式厚膜电阻器-0.0625W-330OHM-+/-1%-0402-BT; %208%%161%%192%%224%%195%%251%%179%%198%: 片式厚膜电阻器; %215%%232%%214%%181%%212%%202%%208%%237%%198%%171%%178%%238%: +/-1%; CODE: 7091333; COMPONENT_HIGH_MAX: 0.4MM; DEVICE: RC_02W3300FT
R135 R136 = R_0: %182%%238%%182%%168%%185%%166%%194%%202%(W): 0.06; %195%%232%%202%%246%: 片式厚膜电阻器-0.0625W-10000OHM-±5%-0402; %208%%161%%192%%224%%195%%251%%179%%198%: 片式厚膜电阻器; %215%%232%%214%%181%%212%%202%%208%%237%%198%%171%%178%%238%: ±5%; CODE: 7090815; COMPONENT_HIGH_MAX: 0.4MM; DEVICE: RC_02W103JT
R180-R182 R272 = R_0: %182%%238%%182%%168%%185%%166%%194%%202%(W): 0.13; %195%%232%%202%%246%: 片式厚膜电阻器-0.125W-75OHM-±1%-0805; %208%%161%%192%%224%%195%%251%%179%%198%: 片式厚膜电阻器; %215%%232%%214%%181%%212%%202%%208%%237%%198%%171%%178%%238%: ±1%; CODE: 7090362; DEVICE: RC0805FR_0775R
T2 = 000-7090-37R_0: %195%%232%%202%%246%: LAN变压器-1CT:1CT-0.35MH-0UH-1路-2变压器-100BASE-T接口模块-SMT; %208%%161%%192%%224%%195%%251%%179%%198%: LAN变压器; CODE: 9050085; COMPONENT_HIGH_MAX: 6.2MM; DEVICE: H1102T
U27 = CS2203-25: DEVICE: CS2033-25
C17 C79 = C_0: %182%%238%%182%%168%%185%%164%%215%%247%%181%%231%%209%%185%(V): 50; %195%%232%%202%%246%: SMD陶瓷电容-50V-0.18NF-+/-5%-NPO-0402; %208%%161%%192%%224%%195%%251%%179%%198%: SMD陶瓷电容; CODE: 8070637; COMPONENT_HIGH_MAX: 0.55MM; DEVICE: CC0402JRNPO9BB181
C80 = C_0: %182%%238%%182%%168%%185%%164%%215%%247%%181%%231%%209%%185%(V): 50; %195%%232%%202%%246%: SMD陶瓷电容-50V-0.1NF-±5%-NPO-0402; %208%%161%%192%%224%%195%%251%%179%%198%: SMD陶瓷电容; CODE: 8070450; COMPONENT_HIGH_MAX: 0.55MM; DEVICE: 04025A101JAT2A
D9 = D2-3_A: %195%%232%%202%%246%: 开关二极管-70V-200MA-1.25V-6NS-串联-SOT-23-2 FIT; %208%%161%%192%%224%%195%%251%%179%%198%: 开关二极管; CODE: 15010042; COMPONENT_HIGH_MAX: 1.26MM; DEVICE: BAV99B5003
J34 = MIC6M2_M_3: %195%%232%%202%%246%: 耳机连接器-3.5MM-5PIN-弯式-THT-00486672; CODE: 14240414; COMPONENT_HIGH_MAX: 5MM; DEVICE: 8967_3506ADT_M_A
L6 = L: %195%%232%%202%%246%: 贴片电感器-0.22UH-+/-5%-3.77OHM-0.3A-0402; %208%%161%%192%%224%%195%%251%%179%%198%: 贴片电感器; CODE: 10031264; COMPONENT_HIGH_MAX: 0.55MM; DEVICE: LGHK1005R22J_T
R9 = R_0: %182%%238%%182%%168%%185%%166%%194%%202%(W): 0.06; %195%%232%%202%%246%: 片式厚膜电阻器-0.0625W-75OHM-+/-1%-0402; %208%%161%%192%%224%%195%%251%%179%%198%: 片式厚膜电阻器; %215%%232%%214%%181%%212%%202%%208%%237%%198%%171%%178%%238%: +/-1%; CODE: 7091321; COMPONENT_HIGH_MAX: 0.4MM; DEVICE: RC_02W750FT
C37 C38 C136 C139 C144 C145 C149-C151 C155 = C_0: %182%%238%%182%%168%%185%%164%%215%%247%%181%%231%%209%%185%(V): 16; %195%%232%%202%%246%: SMD陶瓷电容-16V-100NF-+/-10%-X7R-0402-BT; %208%%161%%192%%224%%195%%251%%179%%198%: SMD陶瓷电容; CODE: 8070614; COMPONENT_HIGH_MAX: 0.6MM; DEVICE: RMEMK105BJ104KV_FR
D12 D13 D27 = D_A: %195%%232%%202%%246%: 肖特基二极管-10V-3A-0.24V-SOD323-BT; %208%%161%%192%%224%%195%%251%%179%%198%: 肖特基二极管; CODE: 15010252; COMPONENT_HIGH_MAX: 1.1MM; DEVICE: BAT60BE6327
J26 = WBC1X19S4M2_0: %195%%232%%202%%246%: IO连接器-HDMI 母座-19PIN-弯式-SMT带DIP脚-终端专用; %208%%161%%192%%224%%195%%251%%179%%198%: IO连接器; CODE: 14240146; COMPONENT_HIGH_MAX: 6.38MM; DEVICE: 1827059_3
R8 = R_0: %182%%238%%182%%168%%185%%166%%194%%202%(W): 0.06; %195%%232%%202%%246%: 片式厚膜电阻器-0.0625W-47000OHM-+/-5%-0402-ELOM; %208%%161%%192%%224%%195%%251%%179%%198%: 片式厚膜电阻器; %215%%232%%214%%181%%212%%202%%208%%237%%198%%171%%178%%238%: +/-5%; CODE: 7090819; DEVICE: RC0402JR_0747K
R184 = R_0: %182%%238%%182%%168%%185%%166%%194%%202%(W): 0.06; %195%%232%%202%%246%: 片式厚膜电阻器-0.0625W-27000OHM-+/-5%-0402; %208%%161%%192%%224%%195%%251%%179%%198%: 片式厚膜电阻器; %215%%232%%214%%181%%212%%202%%208%%237%%198%%171%%178%%238%: +/-5%; CODE: 7090852; COMPONENT_HIGH_MAX: 0.4MM; DEVICE: RK73B1ETTP273J
R3 R4 R59 R72 R103 R104 R108 R186 R187 = R_0: %182%%238%%182%%168%%185%%166%%194%%202%(W): 0.06; %195%%232%%202%%246%: 片式厚膜电阻器-0.0625W-2000OHM-+/-1%-0402-BT; %208%%161%%192%%224%%195%%251%%179%%198%: 片式厚膜电阻器; %215%%232%%214%%181%%212%%202%%208%%237%%198%%171%%178%%238%: +/-1%; CODE: 7091354; COMPONENT_HIGH_MAX: 0.4MM; DEVICE: RC_02W2001FT
U4 = CS0806U
U8 = CS0806S
U23 = CS0806S: #: 3
C73-C75 C81 C86 C92 C103 C109 C110 C113 C117 C125 C126 = C_0: %182%%238%%182%%168%%185%%164%%215%%247%%181%%231%%209%%185%(V): 10; %195%%232%%202%%246%: SMD陶瓷电容-10V-100NF-+/-10%-X5R-0402; %208%%161%%192%%224%%195%%251%%179%%198%: SMD陶瓷电容; CODE: 8070561; COMPONENT_HIGH_MAX: 0.55MM; DEVICE: C0402C104K8PAC_7867
C172 C174 = C_0: %182%%238%%182%%168%%185%%164%%215%%247%%181%%231%%209%%185%(V): 50; %195%%232%%202%%246%: SMD陶瓷电容-50V-0.03NF-+/-5%-NPO-0402; %208%%161%%192%%224%%195%%251%%179%%198%: SMD陶瓷电容; CODE: 8070604; COMPONENT_HIGH_MAX: 0.55MM; DEVICE: GRM1555C1H300J
C176 = C_0: %182%%238%%182%%168%%185%%164%%215%%247%%181%%231%%209%%185%(V): 50; %195%%232%%202%%246%: SMD陶瓷电容-50V-0.001NF-+/-0.1PF-NPO-0402-BT; %208%%161%%192%%224%%195%%251%%179%%198%: SMD陶瓷电容; CODE: 8070578; COMPONENT_HIGH_MAX: 0.55MM; DEVICE: GRM1555C1H1R0B
C217 C221 = C_0: %182%%238%%182%%168%%185%%164%%215%%247%%181%%231%%209%%185%(V): 50; %195%%232%%202%%246%: SMD陶瓷电容-50V-0.033NF-+/-5%-NP0-0402-BT; %208%%161%%192%%224%%195%%251%%179%%198%: SMD陶瓷电容; CODE: 8070547; COMPONENT_HIGH_MAX: 0.55MM; DEVICE: CC0402JRNPO9BN330
C226 = C_0: %182%%238%%182%%168%%185%%164%%215%%247%%181%%231%%209%%185%(V): 50; %195%%232%%202%%246%: SMD陶瓷电容-50V-0.01NF-+/-5%-NP0-0402-BT; %208%%161%%192%%224%%195%%251%%179%%198%: SMD陶瓷电容; CODE: 8070530; COMPONENT_HIGH_MAX: 0.56MM; DEVICE: 04025A100JAT2A
LB4 LB5 LB10 LB13 LB15 = LB_v2: %195%%232%%202%%246%: EMI磁珠-+/-25%-220OHM-0.05OHM-2A-0805; %208%%161%%192%%224%%195%%251%%179%%198%: EMI磁珠; CODE: 10070012; COMPONENT_HIGH_MAX: 1.05MM; DEVICE: MGLB2012_220T_LF
R5 R10 R13 R226 = R_0: %182%%238%%182%%168%%185%%166%%194%%202%(W): 0.06; %195%%232%%202%%246%: 片式厚膜电阻器-0.0625W-33OHM-+/-1%-0402; %208%%161%%192%%224%%195%%251%%179%%198%: 片式厚膜电阻器; %215%%232%%214%%181%%212%%202%%208%%237%%198%%171%%178%%238%: +/-1%; CODE: 7090836; COMPONENT_HIGH_MAX: 0.4MM; DEVICE: RC0402FR_0733RL
R24 = R_0: %182%%238%%182%%168%%185%%166%%194%%202%(W): 0.06; %195%%232%%202%%246%: 片式厚膜电阻器-0.0625W-1000000OHM-+/-1%-0402; %208%%161%%192%%224%%195%%251%%179%%198%: 片式厚膜电阻器; %215%%232%%214%%181%%212%%202%%208%%237%%198%%171%%178%%238%: +/-1%; CODE: 7090857; COMPONENT_HIGH_MAX: 0.4MM; DEVICE: RK73H1ETTP1004F
R68 = R_0: %182%%238%%182%%168%%185%%166%%194%%202%(W): 0.06; %195%%232%%202%%246%: 片式厚膜电阻器-0.0625W-150OHM-+/-5%-0402; %208%%161%%192%%224%%195%%251%%179%%198%: 片式厚膜电阻器; %215%%232%%214%%181%%212%%202%%208%%237%%198%%171%%178%%238%: +/-5%; CODE: 7090788; COMPONENT_HIGH_MAX: 0.4MM; DEVICE: RK73B1ELTP151J
R69 = R_0: %182%%238%%182%%168%%185%%166%%194%%202%(W): 0.06; %195%%232%%202%%246%: 片式厚膜电阻器-0.0625W-1000OHM-+/-5%-0402-BT; %208%%161%%192%%224%%195%%251%%179%%198%: 片式厚膜电阻器; %215%%232%%214%%181%%212%%202%%208%%237%%198%%171%%178%%238%: +/-5%; CODE: 7090809; COMPONENT_HIGH_MAX: 0.4MM; DEVICE: RC0402JR_071KL
R83 = R_0: %182%%238%%182%%168%%185%%166%%194%%202%(W): 0.06; %195%%232%%202%%246%: 片式厚膜电阻器-0.0625W-10000OHM-+/-5%-0402-BT; %208%%161%%192%%224%%195%%251%%179%%198%: 片式厚膜电阻器; %215%%232%%214%%181%%212%%202%%208%%237%%198%%171%%178%%238%: +/-5%; CODE: 7090815; COMPONENT_HIGH_MAX: 0.4MM; DEVICE: RC_02W103JT
R141 = R_0: %182%%238%%182%%168%%185%%166%%194%%202%(W): 0.1; %195%%232%%202%%246%: 片式厚膜电阻器-0.1W-0OHM-<50MOHM-0603-1A-BT,TS16949; %208%%161%%192%%224%%195%%251%%179%%198%: 片式厚膜电阻器; %215%%232%%214%%181%%212%%202%%208%%237%%198%%171%%178%%238%: <50MOHM; CODE: 7090522; COMPONENT_HIGH_MAX: 0.6MM; DEVICE: RC0603JR_070RL
U2 = HI3136V100_19
U12 = AZ1117-ADJ_0
X1 = X3: %195%%232%%202%%246%: 晶体谐振器-24MHZ-20PF-+/-30PPM-40OHM-HC-49S; %208%%161%%192%%224%%195%%251%%179%%198%: 晶体谐振器; CODE: 12020090; COMPONENT_HIGH_MAX: 4.2MM; DEVICE: ESB240000F20D33
C1 = C_0: %182%%238%%182%%168%%185%%164%%215%%247%%181%%231%%209%%185%(V): 50; %195%%232%%202%%246%: SMD陶瓷电容-50V-4700NF-+/-20%-X7R-1210; %208%%161%%192%%224%%195%%251%%179%%198%: SMD陶瓷电容; CODE: 8070690; COMPONENT_HIGH_MAX: 2.8MM; DEVICE: C3225X7R1H475MT000E
C57 = C_0: %182%%238%%182%%168%%185%%164%%215%%247%%181%%231%%209%%185%(V): 50; %195%%232%%202%%246%: SMD陶瓷电容-50V-10NF-10%-X7R-0402-终端专用; %208%%161%%192%%224%%195%%251%%179%%198%: SMD陶瓷电容; CODE: 8070970; COMPONENT_HIGH_MAX: 0.55MM; DEVICE: 0402B103K500CT
C58 C64 C78 C104 = C_0: %182%%238%%182%%168%%185%%164%%215%%247%%181%%231%%209%%185%(V): 50; %195%%232%%202%%246%: SMD陶瓷电容-50V-0.039NF-+/-5%-NPO-0402; %208%%161%%192%%224%%195%%251%%179%%198%: SMD陶瓷电容; CODE: 8070605; COMPONENT_HIGH_MAX: 0.55MM; DEVICE: GRM1555C1H390JZ01D
C105 = C_0: %182%%238%%182%%168%%185%%164%%215%%247%%181%%231%%209%%185%(V): 10; %195%%232%%202%%246%: SMD陶瓷电容-10V-10000NF-+/-10% -X7R-1206; %208%%161%%192%%224%%195%%251%%179%%198%: SMD陶瓷电容; CODE: 8070729; COMPONENT_HIGH_MAX: 1.8MM; DEVICE: 1206B106K100CT
C130 C131 C186 C190 C194 C195 C303-C307 = C_0: %182%%238%%182%%168%%185%%164%%215%%247%%181%%231%%209%%185%(V): 10; %195%%232%%202%%246%: SMD陶瓷电容-10V-100NF-+/-10%-X5R-0402; %208%%161%%192%%224%%195%%251%%179%%198%: SMD陶瓷电容; CODE: 8070561; DEVICE: C0402C104K8PAC_7867
C134 C167 = CP_1: %182%%238%%182%%168%%185%%164%%215%%247%%181%%231%%209%%185%(V): 50; %195%%232%%202%%246%: 非固体SMD铝电容-50V-47UF-+/-20%-6.3*7.7-6.6*6.6MM-极性-105DEGC-1000H-圆柱体-温度敏感器件-工艺耐温250DEGC,5S; %208%%161%%192%%224%%195%%251%%179%%198%: 非固体SMD铝电容; CODE: 8120005; COMPONENT_HIGH_MAX: 8MM; DEVICE: MVE50VC470MF80TPE0_63X77
C148 = C_0: %182%%238%%182%%168%%185%%164%%215%%247%%181%%231%%209%%185%(V): 50; %195%%232%%202%%246%: SMD陶瓷电容-50V-0.022NF-+/-5%-NP0-0402-BT; %208%%161%%192%%224%%195%%251%%179%%198%: SMD陶瓷电容; CODE: 8070545; COMPONENT_HIGH_MAX: 0.55MM; DEVICE: RMUMK105CG220JV_F
C163 = C_0: %182%%238%%182%%168%%185%%164%%215%%247%%181%%231%%209%%185%(V): 50; %195%%232%%202%%246%: SMD陶瓷电容-50V-0.47NF-+/-5%-NPO-0402; %208%%161%%192%%224%%195%%251%%179%%198%: SMD陶瓷电容; CODE: 8070582; COMPONENT_HIGH_MAX: 0.55MM; DEVICE: GRM1555C1H471JA01D
C168 C169 C225 = C_0: %182%%238%%182%%168%%185%%164%%215%%247%%181%%231%%209%%185%(V): 50; %195%%232%%202%%246%: SMD陶瓷电容-50V-1NF-+/-10%-X7R-0603; %208%%161%%192%%224%%195%%251%%179%%198%: SMD陶瓷电容; CODE: 8070249; DEVICE: 06035C102KAT2A
C171 = C_0: %182%%238%%182%%168%%185%%164%%215%%247%%181%%231%%209%%185%(V): 25; %195%%232%%202%%246%: SMD陶瓷电容-25V-220NF-+/-10%-X7R-0805; %208%%161%%192%%224%%195%%251%%179%%198%: SMD陶瓷电容; CODE: 8070567; COMPONENT_HIGH_MAX: 1.45MM; DEVICE: C0805C224K3RAC_7800
C175 = C_0: %182%%238%%182%%168%%185%%164%%215%%247%%181%%231%%209%%185%(V): 25; %195%%232%%202%%246%: SMD陶瓷电容-25V-47NF-+/-10%-X7R-0402-所有; %208%%161%%192%%224%%195%%251%%179%%198%: SMD陶瓷电容; CODE: 8070855; COMPONENT_HIGH_MAX: 0.55MM; DEVICE: C0402C473K3RAC7867
C183 = C_0: %182%%238%%182%%168%%185%%164%%215%%247%%181%%231%%209%%185%(V): 25; %195%%232%%202%%246%: SMD陶瓷电容-25V-10000NF-+/-20%-X7R-1206-所有; %208%%161%%192%%224%%195%%251%%179%%198%: SMD陶瓷电容; CODE: 8070865; COMPONENT_HIGH_MAX: 1.8MM; DEVICE: CETMK316B7106ML_T
C241 C534-C538 = C_0: %182%%238%%182%%168%%185%%164%%215%%247%%181%%231%%209%%185%(V): 50; %195%%232%%202%%246%: SMD陶瓷电容-50V-0.01NF-+/-5%-NP0-0402-BT; %208%%161%%192%%224%%195%%251%%179%%198%: SMD陶瓷电容; CODE: 8070530; COMPONENT_HIGH_MAX: 0.55MM; DEVICE: 04025A100JAT2A
C244 = C_0: %182%%238%%182%%168%%185%%164%%215%%247%%181%%231%%209%%185%(V): 50; %195%%232%%202%%246%: SMD陶瓷电容-50V-1000NF-+/-10%-X7R-1206; %208%%161%%192%%224%%195%%251%%179%%198%: SMD陶瓷电容; CODE: 8070728; COMPONENT_HIGH_MAX: 1.9MM; DEVICE: 12065C105KAT2A
C246 = C_0: %182%%238%%182%%168%%185%%164%%215%%247%%181%%231%%209%%185%(V): 25; %195%%232%%202%%246%: SMD陶瓷电容-25V-22NF-+/-10%-X7R-0603; %208%%161%%192%%224%%195%%251%%179%%198%: SMD陶瓷电容; CODE: 8070246; COMPONENT_HIGH_MAX: 0.9MM; DEVICE: CC0603KRX7R8BB223
C287 = C_0: %182%%238%%182%%168%%185%%164%%215%%247%%181%%231%%209%%185%(V): 50; %195%%232%%202%%246%: SMD陶瓷电容-50V-2.2NF-+/-10%-X7R-0402; %208%%161%%192%%224%%195%%251%%179%%198%: SMD陶瓷电容; CODE: 8070557; COMPONENT_HIGH_MAX: 0.56MM; DEVICE: CM05X7R222K50AH
C296 = CP_1: %182%%238%%182%%168%%185%%164%%215%%247%%181%%231%%209%%185%(V): 16; %195%%232%%202%%246%: 非固体SMD铝电容-16V-220UF-±20%-6.3*11-2.5-0.5MM-极性-105DEGC-1000H; %208%%161%%192%%224%%195%%251%%179%%198%: 非固体SMD铝电容; CODE: *; DEVICE: UVZ1C221MED1TD
C414 = C_0: %182%%238%%182%%168%%185%%164%%215%%247%%181%%231%%209%%185%(V): 16; %195%%232%%202%%246%: SMD陶瓷电容-16V-10NF-+/-10%-X7R-0402-BT，TS16949; %208%%161%%192%%224%%195%%251%%179%%198%: SMD陶瓷电容; CODE: 8070449; DEVICE: GRM155R71C103KA01D
C487 = C_0: %182%%238%%182%%168%%185%%164%%215%%247%%181%%231%%209%%185%(V): 6.3; %195%%232%%202%%246%: SMD陶瓷电容-6.3V-1000NF-+/-10%-X5R-0603; %208%%161%%192%%224%%195%%251%%179%%198%: SMD陶瓷电容; CODE: 8070562; DEVICE: CC0603KRX5R5BB105
C531 C532 = C_0: %182%%238%%182%%168%%185%%164%%215%%247%%181%%231%%209%%185%(V): 50; %195%%232%%202%%246%: SMD陶瓷电容-50V-0.027NF-+/-5%-NP0-0402-BT; %208%%161%%192%%224%%195%%251%%179%%198%: SMD陶瓷电容; CODE: 8070546; COMPONENT_HIGH_MAX: 0.55MM; DEVICE: C0402C270J5GAC_7867
C545 = C_0: %182%%238%%182%%168%%185%%164%%215%%247%%181%%231%%209%%185%(V): 50; %195%%232%%202%%246%: SMD陶瓷电容-50V-0.1NF-+/-5%-NPO-0402-BT; %208%%161%%192%%224%%195%%251%%179%%198%: SMD陶瓷电容; CODE: 8070450; COMPONENT_HIGH_MAX: 0.55MM; DEVICE: 04025A101JAT2A
D7 D8 D11 D17 = DSBD: %195%%232%%202%%246%: 肖特基二极管-40V-2A-0.5V-SMB-40A; %208%%161%%192%%224%%195%%251%%179%%198%: 肖特基二极管; CODE: 15010198; COMPONENT_HIGH_MAX: 2.44MM; DEVICE: MBRS240LT3
J16 = JTDA18250
L1 = L: %195%%232%%202%%246%: 贴片电感器-0.0033UH-0.3NH-0.19OHM-0402; %208%%161%%192%%224%%195%%251%%179%%198%: 贴片电感器; CODE: 10031117; COMPONENT_HIGH_MAX: 0.55MM; DEVICE: LL1005_FHL3N3S
L7 = L_E: DEVICE: 22UH
L9 = SWPA4020S1R0NT
L16 = L: %195%%232%%202%%246%: 贴片电感器-0.0033UH-0.3NH-0.19OHM-0402; %208%%161%%192%%224%%195%%251%%179%%198%: 贴片电感器; CODE: 10031117; COMPONENT_HIGH_MAX: 0.65MM; DEVICE: LL1005_FHL3N3S
L21 = L: %195%%232%%202%%246%: 贴片电感器-4.7UH-20%-0.26OHM-0.43A-20DEGC-2.5*1.8MM-; %208%%161%%192%%224%%195%%251%%179%%198%: 贴片电感器; CODE: 10031116; COMPONENT_HIGH_MAX: 2MM; DEVICE: LQLBC2518T4R7M
Q6 = NPN-BEC_1: %195%%232%%202%%246%: 三极管-NPN-40V-200MA-300MW-0.2V-SOT-23-70-BT; %208%%161%%192%%224%%195%%251%%179%%198%: 三极管; COMPONENT_HIGH_MAX: 1.11MM; DEVICE: MMBT3904LT1
R2 = R_0: %182%%238%%182%%168%%185%%166%%194%%202%(W): 0.1; %195%%232%%202%%246%: 片式厚膜电阻器-0.1W-249OHM-±1%-0603; %208%%161%%192%%224%%195%%251%%179%%198%: 片式厚膜电阻器; %215%%232%%214%%181%%212%%202%%208%%237%%198%%171%%178%%238%: ±1%; CODE: 7090640; COMPONENT_HIGH_MAX: 0.55MM; DEVICE: RHS_03K2490FT
R35 = R_0: %182%%238%%182%%168%%185%%166%%194%%202%(W): 0.1; %195%%232%%202%%246%: 片式厚膜电阻器-0.1W-150000OHM-+/-1%-0603; %208%%161%%192%%224%%195%%251%%179%%198%: 片式厚膜电阻器; %215%%232%%214%%181%%212%%202%%208%%237%%198%%171%%178%%238%: +/-1%; CODE: 7091239; COMPONENT_HIGH_MAX: 0.55MM; DEVICE: RK73H1JTTD1503F
R51 = R_0: %182%%238%%182%%168%%185%%166%%194%%202%(W): 0.1; %195%%232%%202%%246%: 片式厚膜电阻器-0.1W-19600OHM-+/-1%-0603; %208%%161%%192%%224%%195%%251%%179%%198%: 片式厚膜电阻器; %215%%232%%214%%181%%212%%202%%208%%237%%198%%171%%178%%238%: +/-1%; CODE: 7090707; COMPONENT_HIGH_MAX: 0.55MM; DEVICE: RC0603FR_0719K6
R60 = R_0: %182%%238%%182%%168%%185%%166%%194%%202%(W): 0.06; %195%%232%%202%%246%: 片式厚膜电阻器-0.0625W-220OHM-+/-5%-0402-BT; %208%%161%%192%%224%%195%%251%%179%%198%: 片式厚膜电阻器; %215%%232%%214%%181%%212%%202%%208%%237%%198%%171%%178%%238%: +/-5%; CODE: 7090808; COMPONENT_HIGH_MAX: 0.4MM; DEVICE: RC0402JR_07220R
R65 R66 = R_0: %182%%238%%182%%168%%185%%166%%194%%202%(W): 0.06; %195%%232%%202%%246%: 片式厚膜电阻器-0.0625W-2000OHM-+/-1%-0402; %208%%161%%192%%224%%195%%251%%179%%198%: 片式厚膜电阻器; %215%%232%%214%%181%%212%%202%%208%%237%%198%%171%%178%%238%: +/-1%; CODE: 7091354; COMPONENT_HIGH_MAX: 0.4MM; DEVICE: RC_02W2001FT
R92 = R_0: %182%%238%%182%%168%%185%%166%%194%%202%(W): 0.06; %195%%232%%202%%246%: 片式厚膜电阻器-0.0625W-10000OHM-+/-1%-0402-BT; %208%%161%%192%%224%%195%%251%%179%%198%: 片式厚膜电阻器; %215%%232%%214%%181%%212%%202%%208%%237%%198%%171%%178%%238%: +/-1%; CODE: 7090867; COMPONENT_HIGH_MAX: 0.4MM; DEVICE: RK73H1ETTP1002F
R112 = R_0: %182%%238%%182%%168%%185%%166%%194%%202%(W): 0.06; %195%%232%%202%%246%: 片式厚膜电阻器-0.0625W-150OHM-+/-1%-0402--供电专用 07091327-供电专用; %208%%161%%192%%224%%195%%251%%179%%198%: 片式厚膜电阻器; %215%%232%%214%%181%%212%%202%%208%%237%%198%%171%%178%%238%: +/-1%; CODE: 7091730; COMPONENT_HIGH_MAX: 0.4MM; DEVICE: RC0402FR_07150RL
R114 R116 = R_0: %182%%238%%182%%168%%185%%166%%194%%202%(W): 0.1; %195%%232%%202%%246%: 片式厚膜电阻器-0.1W-2000OHM-+/-5%-0603; %208%%161%%192%%224%%195%%251%%179%%198%: 片式厚膜电阻器; %215%%232%%214%%181%%212%%202%%208%%237%%198%%171%%178%%238%: +/-5%; CODE: 7090643; COMPONENT_HIGH_MAX: 0.55MM; DEVICE: RC0603JR_072K
R117 R121 R123 = R_0: %182%%238%%182%%168%%185%%166%%194%%202%(W): 0.06; %195%%232%%202%%246%: 片式厚膜电阻器-0.0625W-75000OHM-+/-1%-0402; %208%%161%%192%%224%%195%%251%%179%%198%: 片式厚膜电阻器; %215%%232%%214%%181%%212%%202%%208%%237%%198%%171%%178%%238%: +/-1%; CODE: 7091008; COMPONENT_HIGH_MAX: 0.4MM; DEVICE: RK73H1ETTD7502F
U14 = LM1117-ADJ_2: CODE: 99051CGJ
U17 = MP8126
U34 = AV2012_14
X4 = X3: %195%%232%%202%%246%: 晶体谐振器-27MHZ-20PF-+/-30PPM-40OHM-SMD; %208%%161%%192%%224%%195%%251%%179%%198%: 晶体谐振器; CODE: 12020090; DEVICE: ESB240000F20D33

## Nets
1V2_ADC_S: C125.1(A) C209.1(A) LB13.2 U2.33(ADC_VDD12)
1V2_APLL_S: C126.1(A) C210.1(A) LB15.2 U2.28(AVDD12_PLL)
1V2_DVDD_S: C109.1(A) C110.1(A) C113.1(A) C117.1(A) C205.1(A) LB10.2 U2.7(DVDD12_1) U2.17(DVDD12_2) U2.25(DVDD12_3) U2.42(DVDD12_4)
3V3: J18.4 R135.1(A) R136.2(B) ; also on sheet 4 5 6 9 15
3V3_AVDD_S: C86.1(A) C201.1(A) LB5.2 R69.1(A) U2.30(AVDD33_PLL)
3V3_DVDD_S: C73.1(A) C74.1(A) C75.1(A) C81.1(A) C200.1(A) LB4.2 R103.2(B) U2.4(DVDD33_1) U2.11(DVDD33_2) U2.19(DVDD33_3) U2.45(DVDD33_4)
3V3_MOS: C92.1(A) C202.1(A) D9.2(K) D12.2(A) J25.10 J25.12 L21.1(A) LB4.1 LB5.1 R35.1(A) R65.1(A) R66.1(A) R104.1(A) R108.1(A) R116.2(B) R218.1(A) R219.1(A) U12.3(VIN) ; also on sheet 5 6 7 8 9 13 14 15 22
3V3_RF: C57.1(A) C144.1(A) C169.2(B) C195.2(B) C296.1 L21.2(B) R112.2(B) U14.2(VOUT1) U14.4(VOUT2) U34.23(VCCREG1) U34.28(VCCREG2)
5V0_MOS: D13.2(A) LB47.1 LB49.1 R179.1(A) ; also on sheet 5 6 14 22
5V0_MOS_HDMI: C150.1(A) D13.1(K) J26.18 R186.2(B) R187.2(B) U4.5(VDD)
5V0_SPDIF: C159.1(A) LB49.2 U9.2(VCC)
12V0_MOS: C136.1(A) C183.1(A) L7.1 R117.1(A) R121.1(A) U17.3(VDD) ; also on sheet 5 6
GND: C1.2(B) C17.2(B) C23.2(B) C33.1(A) C37.2(B) C38.2(B) C57.2(B) C58.2(B) C73.2(B) C74.2(B) C75.2(B) C78.2(B) C79.2(B) C81.2(B) C86.2(B) C92.2(B) C103.2(B) C104.2(B) C105.2(B) C109.2(B) C110.2(B) C113.2(B) C117.2(B) C125.2(B) C126.2(B) C130.2(B) C131.2(B) C134.2 C136.2(B) C140.2(B) C144.2(B) C145.2(B) C147.2(B) C148.2(B) C149.2(B) C150.2(B) C151.2(B) C153.2(B) C154.2(B) C158.2(B) C159.2(B) C163.1(A) C166.2(B) C167.2 C168.1(A) C169.1(A) C170.2(B) C171.1(A) C172.2(B) C174.2(B) C176.2(B) C183.2(B) C190.2(B) C194.2(B) C195.1(A) C200.2(B) C201.2(B) C202.2(B) C204.2(B) C205.2(B) C209.2(B) C210.2(B) C217.2(B) C221.2(B) C225.1(A) C226.2(B) C241.2(B) C244.2(B) C246.2(B) C287.2(B) C288.2(B) C296.2 C297.2(B) C304.1(A) C305.1(A) C316.2(B) C317.2(B) C320.2(B) C339.2(B) C363.2(B) C414.2(B) C487.1(A) C531.2(B) C532.2(B) C534.2(B) C535.2(B) C536.2(B) C537.2(B) C538.2(B) C545.2(B) D9.1(A) D11.1(A) J16.3(GND1) J16.4(GND2) J16.5(GND3) J16.6(GND4) J16.7(GND5) J16.8(GND6) J18.1 J26.2 J26.5 J26.8 J26.11 J26.17 J26.20(S1) J26.21(S2) J26.22(S3) J26.23(S4) J34.5 L16.1(A) Q6.2(E) R2.2(B) R3.2(B) R4.2(B) R8.1(A) R9.2(B) R59.2(B) R64.2(B) R72.2(B) R83.2(B) R92.2(B) R94.2(B) R102.1(A) R123.2(B) R138.2(B) R141.2(B) R145.2(B) R146.2(B) R183.2(B) R229.2(B) U2.29(PLL_GND) U2.34(ADC_GND) U2.47(GND) U2.49(SINK) U4.2(GND) U5.1(+INR) U5.4(SGND) U5.10(PGND) U5.14(+INL) U8.3(GND1) U8.8(GND2) U9.3(GND) U17.1(SGND) U17.16(PGND) U17.17(SINK) U23.3(GND1) U23.8(GND2) U34.29(EPAD) ; also on sheet 3 4 5 6 7 8 9 10 11 12 13 14 15 22
VDD_AUDIO: C158.1(A) C320.1(A) R139.2(B) R174.1(A) R179.2(B) U5.9(PVDD)
3136_ADDR0: R3.1(A) U2.39(ADDR0)
3136_ADDR1: R103.1(A) U2.38(ADDR1)
3136_DISEQC_IN: Q6.3(C) R51.1(A) R116.1(A) U2.13(DISEQC_IN)
3136_DISEQC_OUT: R123.1(A) U2.12(DISEQC_OUT) U17.9(EXTM)
3136_FUNC_SEL: R4.1(A) U2.14(FUNC_SEL)
3136_HV_SEL: U2.18(HV_SEL) U17.8(13V/18V)
3136_I2C_SCL: C221.1(A) R108.2(B) U2.41(SCL) ; also on sheet 6
3136_I2C_SDA: C217.1(A) R104.2(B) U2.40(SDA) ; also on sheet 6
3136_IOUT_N: C307.2(B) U2.32(VINNI)
3136_IOUT_P: C303.2(B) U2.31(VINPI)
3136_LNB_EN: U2.21(LNB_EN) U17.5(EN)
3136_QOUT_N: C186.2(B) U2.35(VINNQ)
3136_QOUT_P: C306.2(B) U2.36(VINPQ)
3136_RF_AGC: C37.1(A) R60.1(A) R127.2(B)
3136_RSTN: C38.1(A) R83.1(A) U2.15(RSTN) ; also on sheet 6
3136_TS_CLK: R10.2(B) U2.46(TS_CLK)
3136_TS_OUT0: R13.2(B) U2.48(TS_OUT0)
3136_TS_SYNC: R226.2(B) U2.43(TS_SYNC)
3136_TS_VAL: C176.1(A) R5.2(B) U2.44(TS_VALID)
3136_XIN: C172.1(A) R24.1(A) U2.23(XIN) X1.2
3136_XOUT: C174.1(A) R24.2(B) U2.22(XOUT) X1.1
AC2012_SCL_T: R61.2(B) R65.2(B) U2.27(SCLT)
AC2012_SDA_T: R62.2(B) R66.2(B) U2.26(SDAT)
ADAC_VOUTL: C350.2(B) R138.1(A) ; also on sheet 7
ADAC_VOUTR: C351.1(A) R183.1(A) ; also on sheet 7
AUDIO_L: C339.1(A) J34.3 R119.2(B)
AUDIO_R: C140.1(A) J34.2 R74.1(A)
CVBS: C79.1(A) C80.1(A) L6.1(A) R9.1(A) ; also on sheet 7
CVBS_OUT: C17.1(A) C80.2(B) D9.3(COM) J34.4 L6.2(B)
HDMI_TX0N: J26.9 U8.2(IO2_IN) U8.9(IO2_OUT) ; also on sheet 7
HDMI_TX0P: J26.7 U8.1(IO1_IN) U8.10(IO1_OUT) ; also on sheet 7
HDMI_TX1N: J26.6 U23.5(IO4_IN) U23.6(IO4_OUT) ; also on sheet 7
HDMI_TX1P: J26.4 U23.4(IO3_IN) U23.7(IO3_OUT) ; also on sheet 7
HDMI_TX2N: J26.3 U23.2(IO2_IN) U23.9(IO2_OUT) ; also on sheet 7
HDMI_TX2P: J26.1 U23.1(IO1_IN) U23.10(IO1_OUT) ; also on sheet 7
HDMI_TX_CEC: J26.13 R184.2(B) U4.3(I/O2) ; also on sheet 7
HDMI_TX_HOTPLUG: C149.1(A) J26.19 R8.2(B) U4.4(I/O3) ; also on sheet 7
HDMI_TX_SCL: J26.15 R186.1(A) U4.1(I/O1) ; also on sheet 7
HDMI_TX_SDA: J26.16 R187.1(A) U4.6(I/O4) ; also on sheet 7
HDMI_TXCN: J26.12 U8.5(IO4_IN) U8.6(IO4_OUT) ; also on sheet 7
HDMI_TXCP: J26.10 U8.4(IO3_IN) U8.7(IO3_OUT) ; also on sheet 7
LED0_BASE: R67.2(B) R219.2(B) ; also on sheet 6
LED0_LINK_ACT: R185.2(B) R218.2(B) ; also on sheet 6
LNB_PWR: C58.1(A) C64.1(A) C78.1(A) C104.1(A) C155.2(B) C170.1(A) D17.2(B) D27.1(K) J16.2(ANT_IN)
LNB_PWR_B: C166.1(A) C287.1(A) C288.1(A) D27.2(A) R166.2(B)
LOOPTHROUGH: C283.1(A) J16.1(LOOP) R166.1(A)
MUTE_CTRL: R90.1(A) ; also on sheet 7
REG2OUT: C130.1(A) C131.1(A) C225.2(B) C414.1(A) U34.1(REG2OUT) U34.2(VCCRF1) U34.5(VCCRF2) U34.10(VCCZIF) U34.25(VCCCP)
RX+_PHY0: R50.1(A) U27.3(IO2_P1) U27.6(IO2_P2) ; also on sheet 6
RX-_PHY0: R18.1(A) U27.4(IO2_N1) U27.5(IO2_N2) ; also on sheet 6
SPDIF_OUT_BOOT_SEL1: U9.1(VIN) ; also on sheet 6 7
TSI1_CLK: R10.1(A) ; also on sheet 6
TSI1_D0: R13.1(A) ; also on sheet 6
TSI1_SYNC: R226.1(A) ; also on sheet 6
TSI1_VALID: R5.1(A) ; also on sheet 6
TX+_PHY0: R80.1(A) U27.1(IO1_P1) U27.8(IO1_P2) ; also on sheet 6
TX-_PHY0: R79.1(A) U27.2(IO1_N1) U27.7(IO1_N2) ; also on sheet 6
UART0_RXD: J18.2 R136.1(A) ; also on sheet 6
UART0_TXD: J18.3 R135.2(B) ; also on sheet 6
N06243: C147.1(A) C153.1(A) T2.2(CTD)
N06255: J25.4 J25.5 R272.2(B)
N06263: J25.2 T2.14(TX-)
N06271: J25.1 T2.16(TX+)
N06279: C23.1(A) R180.1(A) R181.1(A) R182.1(A) R272.1(A)
N06299: J25.3 T2.11(RX+)
N06307: J25.6 T2.9(RX-)
N06311: R180.2(B) T2.10(CRX)
N06317: R181.2(B) T2.15(CTX)
N06323: J25.7 J25.8 R182.2(B)
N06333: J25.11 R185.1(A)
N06337: J25.9 R67.1(A)
N06341: C154.1(A) C297.1(A) T2.7(CRD)
N06383: R80.2(B) T2.1(TD+)
N06387: R79.2(B) T2.3(TD-)
N06391: R50.2(B) T2.6(RD+)
N06427: R18.2(B) T2.8(RD-)
N07148: C363.1(A) R90.2(B) R139.1(A) R229.1(A) U5.5(EN)
N07170: R93.2(B) R94.1(A) R174.2(B)
N07214: C32.2(B) U5.8(CP)
N07222: C33.2(B) U5.6(PVSS)
N07226: C32.1(A) U5.7(CN)
N07242: C54.2(B) R28.1(A) U5.13(-INL)
N07260: C316.1(A) R28.2(B) R97.2(B) R194.1(A)
N07272: C350.1(A) R194.2(B)
N07276: C54.1(A) R97.1(A) R119.1(A) R145.1(A) U5.12(OUTL)
N07302: C55.1(A) R27.2(B) U5.2(-INR)
N07312: C55.2(B) R19.2(B) R74.2(B) R146.1(A) U5.3(OUTR)
N07338: C317.1(A) R19.1(A) R27.1(A) R193.2(B)
N07350: C351.2(B) R193.1(A)
N07354: R93.1(A) U5.11(UVP)
N493031: C1.1(A) C139.2(B) D8.2(B) L9.2(B) U17.13(VBOOST)
N493091: D7.1(A) L7.2 U17.15(SW)
N493117: C163.2(B) C175.2(B) U17.4(COMP)
N493231: C303.1(A) C537.1(A) U34.12(RXIP)
N493247: C241.1(A) C307.1(A) U34.11(RXIN)
N493263: C186.1(A) C535.1(A) U34.9(RXQN)
N493279: C306.1(A) C536.1(A) U34.8(RXQP)
N493291: R64.1(A) U34.13(PD)
N493299: R59.1(A) U34.14(ADDR0)
N493307: C538.1(A) R61.1(A) U34.15(SCL)
N493323: C534.1(A) R62.1(A) U34.16(SDA)
N493339: C531.1(A) U34.19(XTAL1) X4.2
N493359: C532.1(A) U34.18(XTAL2) X4.1
N493371: C190.1(A) C194.1(A) U34.20(VCCXO) U34.21(VDDD) U34.22(REG1OUT)
N493545: C282.1(A) C283.2(B) L16.2(B)
N493557: C282.2(B) U34.7(RFLP)
N493569: L1.2(B) R63.1(A) U34.3(RFIN+)
N493581: C545.1(A) R60.2(B) U34.6(RFAGC)
N493597: C148.1(A) U34.4(RFIN-)
N493601: C304.2(B) R63.2(B)
N493605: R72.1(A) U34.17(ADDR1)
N493609: C64.2(B) C305.2(B) L1.1(A)
N493625: R2.1(A) R112.1(A) U14.1(ADJ)
N493633: C105.1(A) C145.1(A) LB47.2 U14.3(VIN)
N493653: C171.2(B) U17.2(BYPASS)
N493657: C175.1(A) R102.2(B)
N493661: R117.2(B) U17.6(LINEDROP)
N493665: R121.2(B) U17.7(POK)
N493727: C139.1(A) U17.14(BST)
N493731: C134.1 D7.2(B) L9.1(A)
N493743: C151.1(A) C167.1 C244.1(A) D8.1(A) D11.2(B) D17.1(A) U17.12(VOUT)
N493787: R92.1(A) U17.11(ILIMIT)
N493791: C246.1(A) U17.10(TCAP)
N493795: Q6.1(B) R51.2(B) R114.1(A)
N493807: C155.1(A) R35.2(B) R114.2(B)
N498441: R69.2(B) R127.1(A) U2.37(AGC)
N498473: C226.1(A) U2.24(CLK_OUT)
N498481: R68.1(A) R141.1(A) U12.1(ADJ)
N498501: C103.1(A) C204.1(A) LB10.1 LB13.1 LB15.1 R68.2(B) U12.2(VOUT1) U12.4(VOUT2)
N501605: D12.1(K) R184.1(A)
N823239: C487.2(B) U34.26(REGCAP2) U34.27(REGCAP1)
N849235: C168.2(B) U34.24(CP)

Not connected (* = marked no-connect by the designer): J25 13(M1) 14(M2); J26 14 24(M1) 25(M2); J34 6(NC) 7(M1) 8(M2); U2 1(TS_OUT1) 2(TS_OUT2) 3(TS_OUT3) 5(TS_OUT4) 6(TS_OUT5) 8(TS_OUT6) 9(TS_OUT7) 10(TS_ERR) 16(FSK_OUT) 20(FSK_IN); U9 4(M1) 5(M2) 6(M3) 7(M4) 8(M5)

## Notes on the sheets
sheet 16
- Audio Output
- 1%
- 1%
- 1%
- 1%
- 1%
- MUTE_CTL
- 0
- Mute
- 1
- Work
- SPDIF
sheet 17
- FE PHY
- Put C153 and C154 close to T2
- UART
sheet 18
- VDAC OUTPUT
- ** Design guideline **
- 1.All channel traces should be separated from other traces by GND.
- 2.ESD components are suggested for ports protection, default BAV99.
sheet 19
- HDMI TX
- ** HDMI Design guideline **
- A.routing
- 1.Route as 100 Ohm differential impedance.
- 2.Differential pairs should be routed on TOP layer only.
- 3.Differential pairs should be separated from other traces by GND .
- B.trace length
- 1.The length for the differential pairs should be less than 5 inches.
- 2.Match trace length of differential pairs, 5 mils max within a pair.
- C.component selection
- 1.ESD components are suggested for ports protection.
- 2.All equivalent capacitance of ESD components should be < 0.8pF.
sheet 20
- Hi3136V100
- 3136 I2C ADDR RD: 0xB5
- WR: 0xB4
- CLose to U2
sheet 21
- DVB-S2 Tuner&LNB Power
- length
- Track1
- 900mil(Point A to Point B)
- Track2
- 350mil(Point B to Point C)
- 75ohm
- A
- 75ohm
- 75ohm
- VO=1.25x(1+249/150)=3.325V
- Track1:90ohm
- Track2:90ohm
- C
- B
- 75ohm
- 1%
- D
- 75ohm
- 75ohm
- 75ohm
- Track4:90ohm
- E
- F
- 1%
- Track3:90ohm
- length
- Track3
- 900mil(Point D to Point E)
- Track4
- 350mil(Point E to Point F)
- [21]
- HV_SEL
- 1
- 19V
- 0
- 14V
